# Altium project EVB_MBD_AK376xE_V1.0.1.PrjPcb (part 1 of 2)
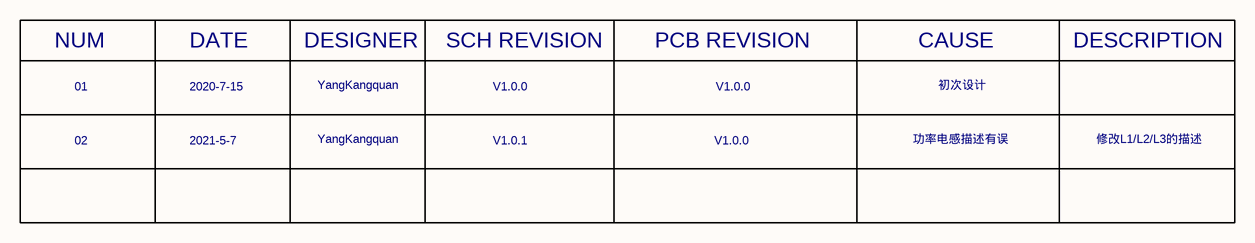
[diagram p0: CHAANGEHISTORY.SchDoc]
8 sheets, 331 parts. Net scope: flat (ports and power ports of the same name join across sheets).
Sheets:
  CHAANGEHISTORY.SchDoc
  BLOCK_DIAGRAM.SchDoc
  INTERFACE_CORE.SchDoc
  POWER.SchDoc
  TF_PA_UART.SchDoc
  MAC_EMMC_USBWIFI.SchDoc
  LCD.SchDoc
  JTAG_I2S_KEY.SchDoc

## Sheet CHAANGEHISTORY.SchDoc: EVB_MBD_AK376xE_V1.0.1
size A3; Revision: V1.0.1; SheetNumber: 1; SheetTotal: 8

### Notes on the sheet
- NUM
- 01
- DATE
- 2020-7-15
- DESIGNER
- YangKangquan
- SCH REVISION
- V1.0.0
- PCB REVISION
- CAUSE
- 初次设计
- DESCRIPTION
- 02
- 2021-5-7
- V1.0.1
- 功率电感描述有误
- 修改L1/L2/L3的描述

## Sheet BLOCK_DIAGRAM.SchDoc: EVB_MBD_AK376xE_V1.0.1
size A3; Revision: V1.0.1; SheetNumber: 2; SheetTotal: 8
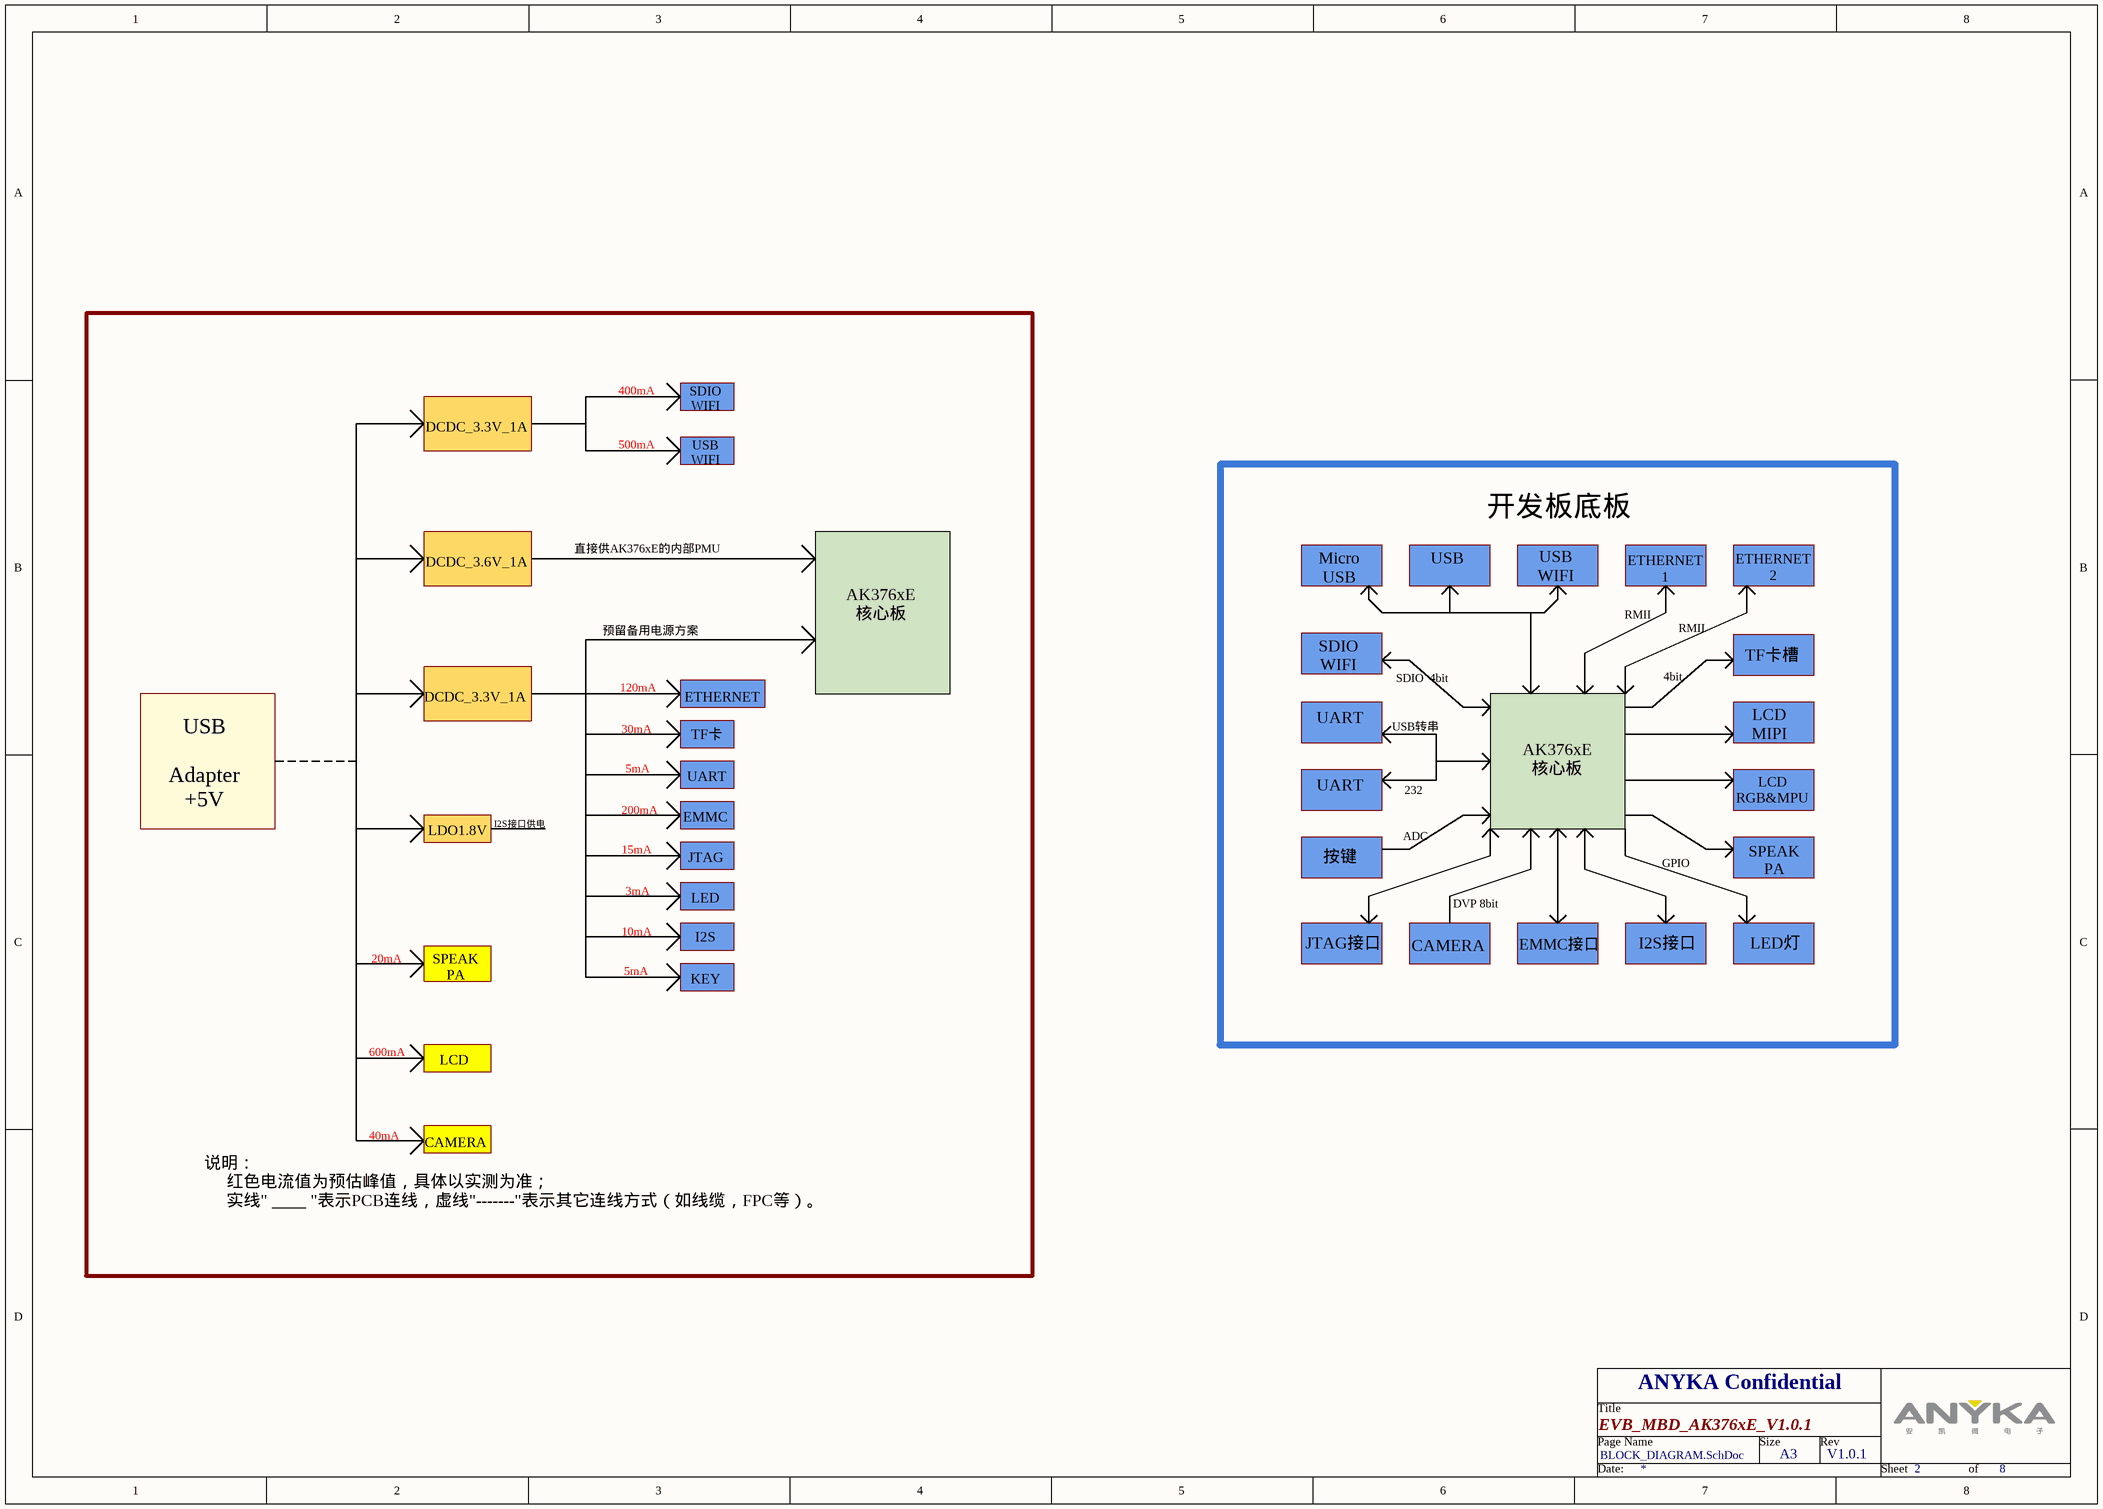
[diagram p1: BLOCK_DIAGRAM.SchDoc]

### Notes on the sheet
- DCDC_3.3V_1A
- 400mA
- 500mA
- SDIO
  WIFI
- USB
  WIFI
- DCDC_3.6V_1A
- 直接供AK376xE的内部PMU
- Micro
  USB
- USB
  HOST
- 开发板底板
- ETHERNET
  1
- ETHERNET
  2
- 预留备用电源方案
- AK376xE
  核心板
- RMII
- 120mA
- ETHERNET
- SDIO  4bit
- 4bit
- TF卡槽
- 30mA
- 5mA
- TF卡
- UART
- UART
  USB
- USB转串
- LCD
  MIPI
- USB
  Adapter
  +5V
- LDO1.8V
- I2S接口供电
- 15mA
- 200mA
- EMMC
- JTAG
- UART
  DB9
- ADC
- 232
- LCD
  RGB&MPU
- 3mA
- LED
- 按键
- DVP 8bit
- GPIO
- SPEAK
  PA
- 20mA
- 10mA
- I2S
- KEY
- JTAG接口
- CAMERA
- EMMC接口
- I2S接口
- LED灯
- 600mA
- LCD
- 40mA
- 说明：
  红色电流值为预估峰值，具体以实测为准；
  实线" ____ "表示PCB连线，虚线"-------"表示其它连线方式（如线缆，FPC等）。

## Sheet INTERFACE_CORE.SchDoc: EVB_MBD_AK376xE_V1.0.1
size A3; Revision: V1.0.1; SheetNumber: 3; SheetTotal: 8
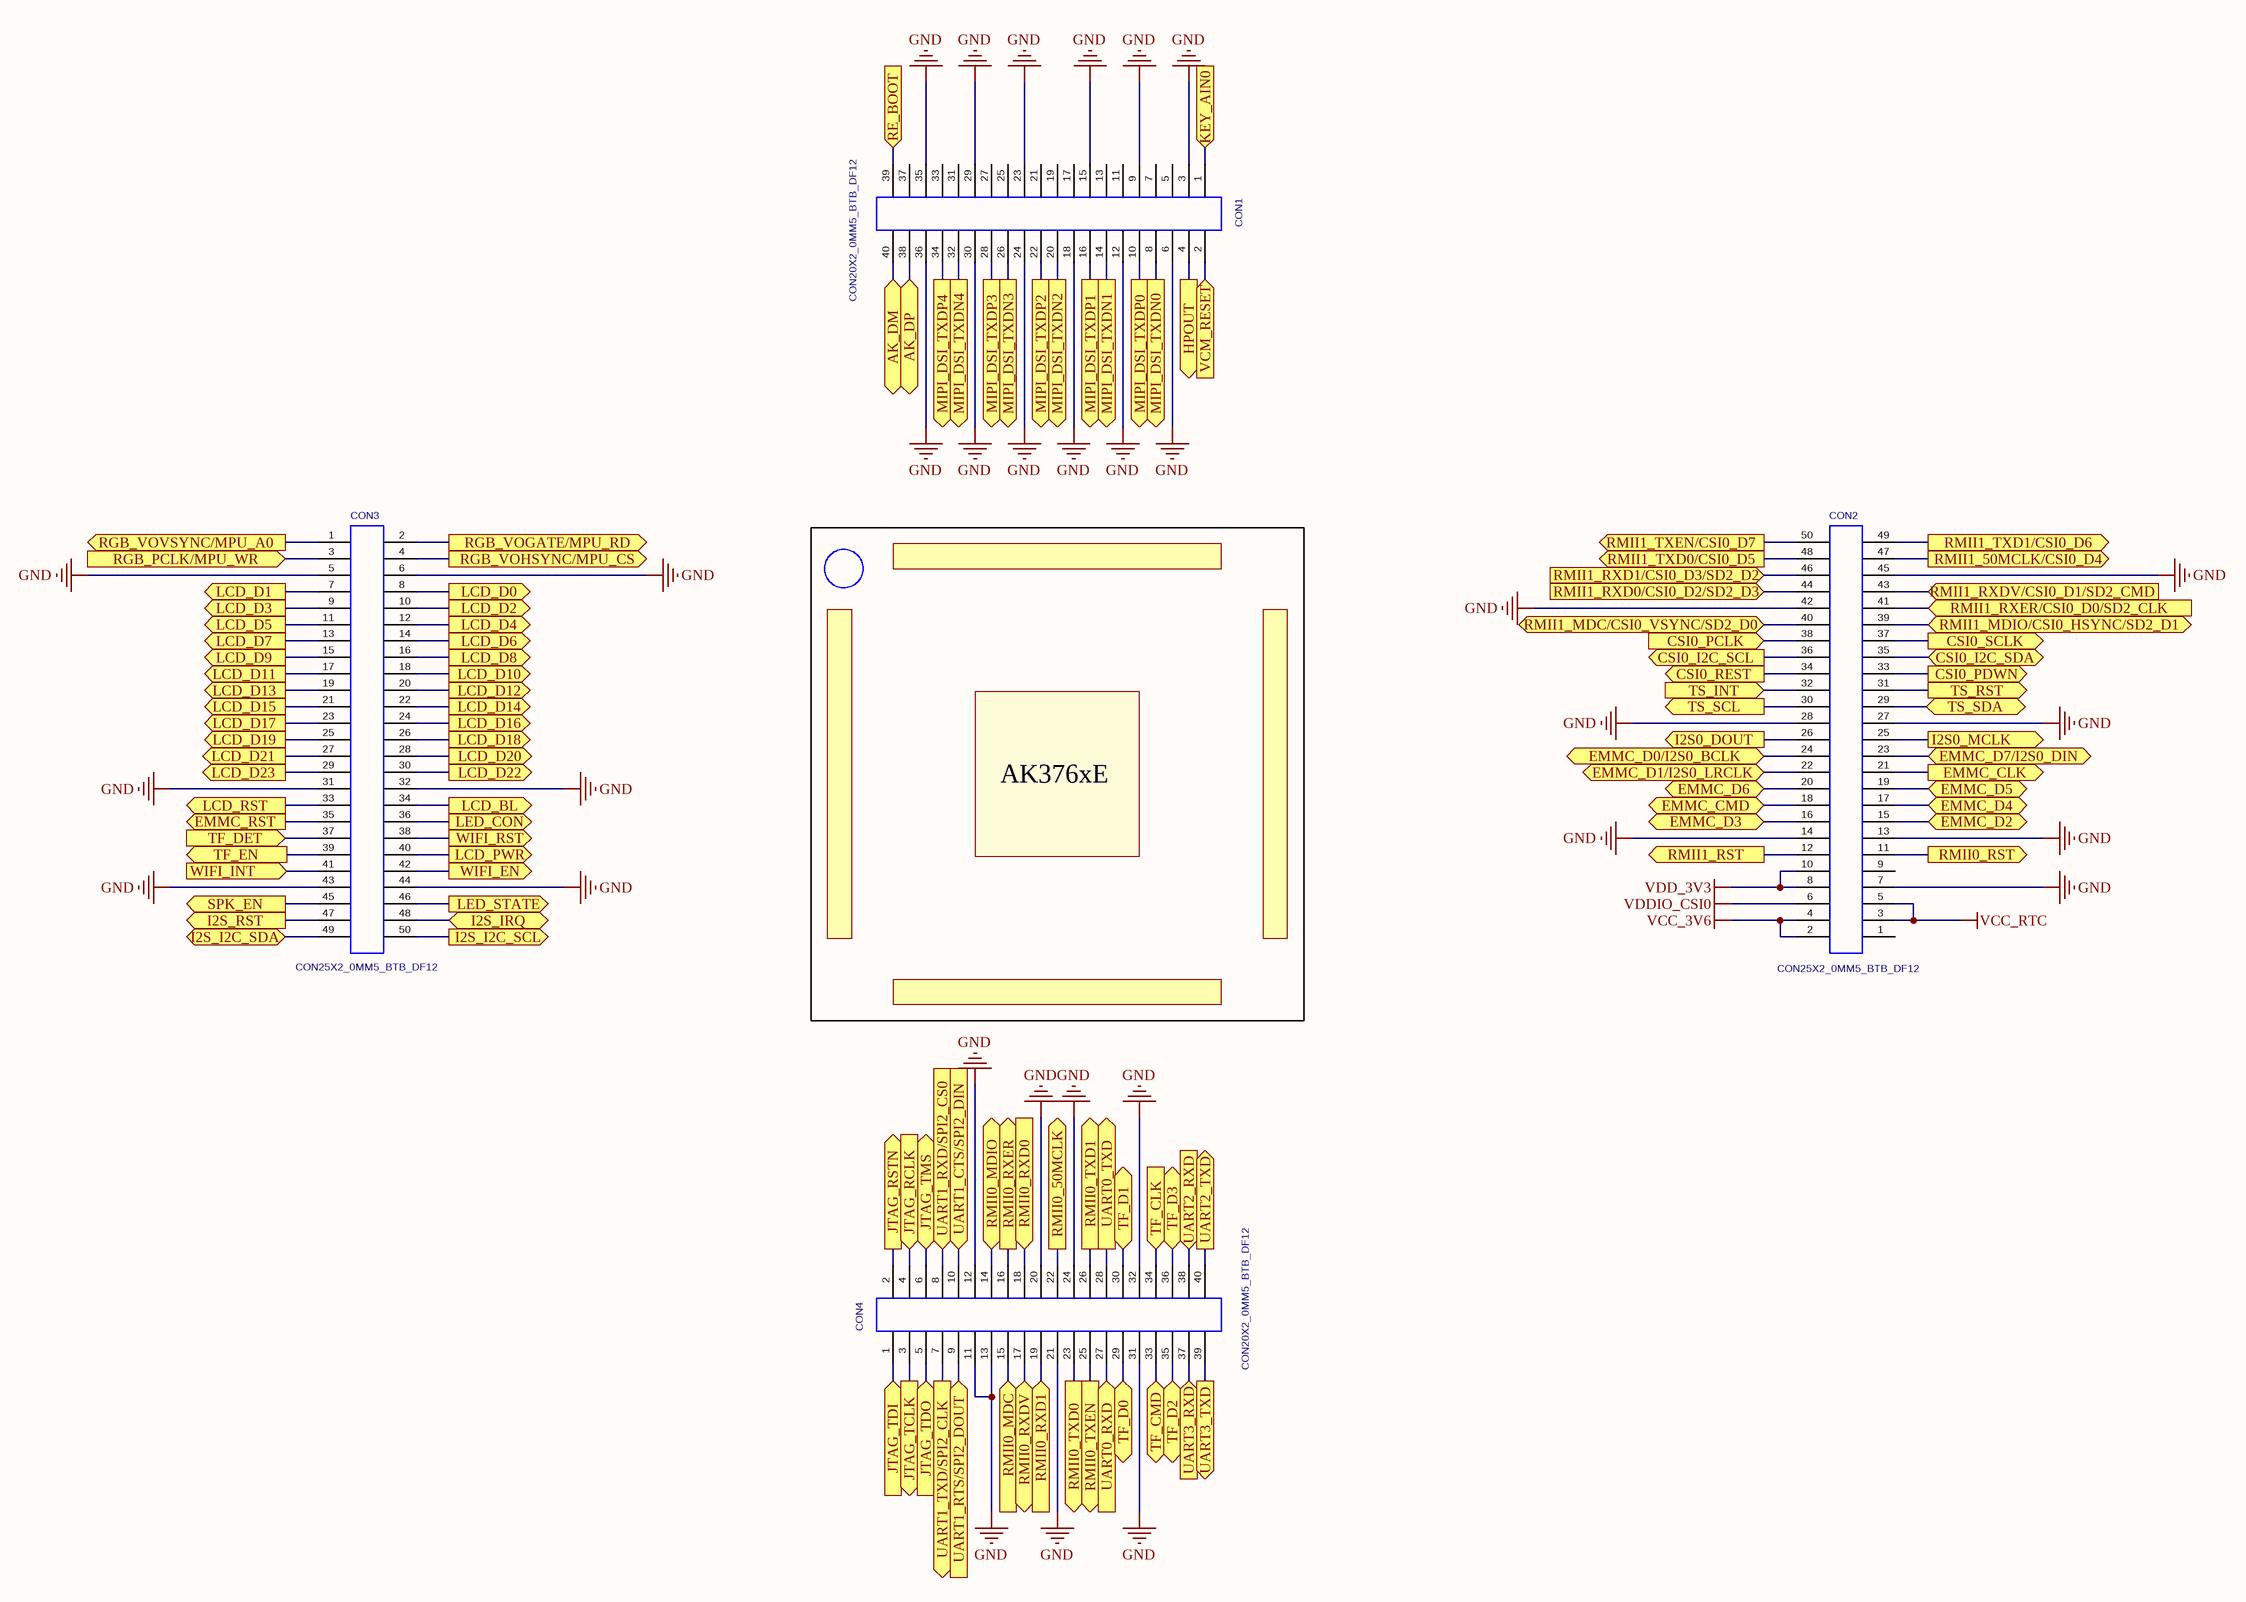
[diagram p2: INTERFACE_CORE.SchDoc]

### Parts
CON1  CON20X2_0MM5_BTB_DF12  [CON20X2_0MM5_BTB_DF12_P]
CON2  CON25X2_0MM5_BTB_DF12  [CON25X2_0MM5_BTB_DF12_P]
CON3  CON25X2_0MM5_BTB_DF12  [CON25X2_0MM5_BTB_DF12_P]
CON4  CON20X2_0MM5_BTB_DF12  [CON20X2_0MM5_BTB_DF12_P]

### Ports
AK_DM (bidir), AK_DP (bidir), CSI0_I2C_SCL (out), CSI0_I2C_SDA (bidir), CSI0_PCLK (in), CSI0_PDWN (out), CSI0_REST (out), CSI0_SCLK (out), EMMC_CLK (out), EMMC_CMD (bidir), EMMC_D0/I2S0_BCLK (bidir), EMMC_D1/I2S0_LRCLK (bidir), EMMC_D2 (bidir), EMMC_D3 (bidir), EMMC_D4 (bidir), EMMC_D5 (bidir), EMMC_D6 (bidir), EMMC_D7/I2S0_DIN (bidir), EMMC_RST (out), HPOUT (out), I2S0_DOUT (out), I2S0_MCLK (out), I2S_I2C_SCL (out), I2S_I2C_SDA (bidir), I2S_IRQ (bidir), I2S_RST (out), JTAG_RCLK (in), JTAG_RSTN (out), JTAG_TCLK (out), JTAG_TDI (in), JTAG_TDO (in), JTAG_TMS (bidir), KEY_AIN0 (in), LCD_BL (out), LCD_D0 (out), LCD_D1 (out), LCD_D2 (out), LCD_D3 (out), LCD_D4 (out), LCD_D5 (out), LCD_D6 (out), LCD_D7 (out), LCD_D8 (out), LCD_D9 (out), LCD_D10 (out), LCD_D11 (out), LCD_D12 (out), LCD_D13 (out), LCD_D14 (out), LCD_D15 (out), LCD_D16 (out), LCD_D17 (out), LCD_D18 (out), LCD_D19 (out), LCD_D20 (out), LCD_D21 (out), LCD_D22 (out), LCD_D23 (out), LCD_PWR (out), LCD_RST (out), LED_CON (out), LED_STATE (out), MIPI_DSI_TXDN0 (out), MIPI_DSI_TXDN1 (out), MIPI_DSI_TXDN2 (out), MIPI_DSI_TXDN3 (out), MIPI_DSI_TXDN4 (out), MIPI_DSI_TXDP0 (out), MIPI_DSI_TXDP1 (out), MIPI_DSI_TXDP2 (out), MIPI_DSI_TXDP3 (out), MIPI_DSI_TXDP4 (out), RE_BOOT (in), RGB_PCLK/MPU_WR (in), RGB_VOGATE/MPU_RD (out), RGB_VOHSYNC/MPU_CS (out), RGB_VOVSYNC/MPU_A0 (out), RMII0_50MCLK (out), RMII0_MDC (in), RMII0_MDIO (bidir), RMII0_RST (out), RMII0_RXD0 (in), RMII0_RXD1 (in), RMII0_RXDV (bidir), RMII0_RXER (out), RMII0_TXD0 (out), RMII0_TXD1 (out), RMII0_TXEN (out), RMII1_50MCLK/CSI0_D4 (out), RMII1_MDC/CSI0_VSYNC/SD2_D0 (bidir), RMII1_MDIO/CSI0_HSYNC/SD2_D1 (bidir), RMII1_RST (out), RMII1_RXD0/CSI0_D2/SD2_D3 (in), RMII1_RXD1/CSI0_D3/SD2_D2 (in), RMII1_RXDV/CSI0_D1/SD2_CMD (in), RMII1_RXER/CSI0_D0/SD2_CLK (in), RMII1_TXD0/CSI0_D5 (out), RMII1_TXD1/CSI0_D6 (out), RMII1_TXEN/CSI0_D7 (out), SPK_EN (out), TF_CLK (in), TF_CMD (bidir), TF_D0 (bidir), TF_D1 (bidir), TF_D2 (bidir), TF_D3 (bidir), TF_DET (in), TF_EN (out), TS_INT (in), TS_RST (out), TS_SCL (out), TS_SDA (bidir), UART0_RXD (in), UART0_TXD (out), UART1_CTS/SPI2_DIN (in), UART1_RTS/SPI2_DOUT (in), UART1_RXD/SPI2_CS0 (in), UART1_TXD/SPI2_CLK (out), UART2_RXD (in), UART2_TXD (out), UART3_RXD (in), UART3_TXD (out), VCM_RESET (in), WIFI_EN (out), WIFI_INT (in), WIFI_RST (out)

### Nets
GND: CON1.3 CON1.6 CON1.9 CON1.12 CON1.15 CON1.18 CON1.23 CON1.24 CON1.29 CON1.30 CON1.35 CON1.36 CON2.7 CON2.13 CON2.14 CON2.27 CON2.28 CON2.42 CON2.45 CON3.5 CON3.6 CON3.31 CON3.32 CON3.43 CON3.44 CON4.11 CON4.12 CON4.13 CON4.20 CON4.21 CON4.24 CON4.31 CON4.32
VCC_3V6: CON2.2 CON2.4
VCC_RTC: CON2.3 CON2.5
VDD_3V3: CON2.8 CON2.10
VDDIO_CSI0: CON2.6
AK_DM: CON1.40 ; port AK_DM
AK_DP: CON1.38 ; port AK_DP
CSI0_I2C_SCL: CON2.36 ; port CSI0_I2C_SCL
CSI0_I2C_SDA: CON2.35 ; port CSI0_I2C_SDA
CSI0_PCLK: CON2.38 ; port CSI0_PCLK
CSI0_PDWN: CON2.33 ; port CSI0_PDWN
CSI0_REST: CON2.34 ; port CSI0_REST
CSI0_SCLK: CON2.37 ; port CSI0_SCLK
EMMC_CLK: CON2.21 ; port EMMC_CLK
EMMC_CMD: CON2.18 ; port EMMC_CMD
EMMC_D0/I2S0_BCLK: CON2.24 ; port EMMC_D0/I2S0_BCLK
EMMC_D1/I2S0_LRCLK: CON2.22 ; port EMMC_D1/I2S0_LRCLK
EMMC_D2: CON2.15 ; port EMMC_D2
EMMC_D3: CON2.16 ; port EMMC_D3
EMMC_D4: CON2.17 ; port EMMC_D4
EMMC_D5: CON2.19 ; port EMMC_D5
EMMC_D6: CON2.20 ; port EMMC_D6
EMMC_D7/I2S0_DIN: CON2.23 ; port EMMC_D7/I2S0_DIN
EMMC_RST: CON3.35 ; port EMMC_RST
HPOUT: CON1.4 ; port HPOUT
I2S0_DOUT: CON2.26 ; port I2S0_DOUT
I2S0_MCLK: CON2.25 ; port I2S0_MCLK
I2S_I2C_SCL: CON3.50 ; port I2S_I2C_SCL
I2S_I2C_SDA: CON3.49 ; port I2S_I2C_SDA
I2S_IRQ: CON3.48 ; port I2S_IRQ
I2S_RST: CON3.47 ; port I2S_RST
JTAG_RCLK: CON4.4 ; port JTAG_RCLK
JTAG_RSTN: CON4.2 ; port JTAG_RSTN
JTAG_TCLK: CON4.3 ; port JTAG_TCLK
JTAG_TDI: CON4.1 ; port JTAG_TDI
JTAG_TDO: CON4.5 ; port JTAG_TDO
JTAG_TMS: CON4.6 ; port JTAG_TMS
LCD_BL: CON3.34 ; port LCD_BL
LCD_D0: CON3.8 ; port LCD_D0
LCD_D1: CON3.7 ; port LCD_D1
LCD_D2: CON3.10 ; port LCD_D2
LCD_D3: CON3.9 ; port LCD_D3
LCD_D4: CON3.12 ; port LCD_D4
LCD_D5: CON3.11 ; port LCD_D5
LCD_D6: CON3.14 ; port LCD_D6
LCD_D7: CON3.13 ; port LCD_D7
LCD_D8: CON3.16 ; port LCD_D8
LCD_D9: CON3.15 ; port LCD_D9
LCD_D10: CON3.18 ; port LCD_D10
LCD_D11: CON3.17 ; port LCD_D11
LCD_D12: CON3.20 ; port LCD_D12
LCD_D13: CON3.19 ; port LCD_D13
LCD_D14: CON3.22 ; port LCD_D14
LCD_D15: CON3.21 ; port LCD_D15
LCD_D16: CON3.24 ; port LCD_D16
LCD_D17: CON3.23 ; port LCD_D17
LCD_D18: CON3.26 ; port LCD_D18
LCD_D19: CON3.25 ; port LCD_D19
LCD_D20: CON3.28 ; port LCD_D20
LCD_D21: CON3.27 ; port LCD_D21
LCD_D22: CON3.30 ; port LCD_D22
LCD_D23: CON3.29 ; port LCD_D23
LCD_PWR: CON3.40 ; port LCD_PWR
LCD_RST: CON3.33 ; port LCD_RST
LED_CON: CON3.36 ; port LED_CON
LED_STATE: CON3.46 ; port LED_STATE
MIPI_DSI_TXDN0: CON1.8 ; port MIPI_DSI_TXDN0
MIPI_DSI_TXDN1: CON1.14 ; port MIPI_DSI_TXDN1
MIPI_DSI_TXDN2: CON1.20 ; port MIPI_DSI_TXDN2
MIPI_DSI_TXDN3: CON1.26 ; port MIPI_DSI_TXDN3
MIPI_DSI_TXDN4: CON1.32 ; port MIPI_DSI_TXDN4
MIPI_DSI_TXDP0: CON1.10 ; port MIPI_DSI_TXDP0
MIPI_DSI_TXDP1: CON1.16 ; port MIPI_DSI_TXDP1
MIPI_DSI_TXDP2: CON1.22 ; port MIPI_DSI_TXDP2
MIPI_DSI_TXDP3: CON1.28 ; port MIPI_DSI_TXDP3
MIPI_DSI_TXDP4: CON1.34 ; port MIPI_DSI_TXDP4
RE_BOOT: CON1.39 ; port RE_BOOT
RGB_PCLK/MPU_WR: CON3.3 ; port RGB_PCLK/MPU_WR
RGB_VOGATE/MPU_RD: CON3.2 ; port RGB_VOGATE/MPU_RD
RGB_VOHSYNC/MPU_CS: CON3.4 ; port RGB_VOHSYNC/MPU_CS
RGB_VOVSYNC/MPU_A0: CON3.1 ; port RGB_VOVSYNC/MPU_A0
RMII0_50MCLK: CON4.22 ; port RMII0_50MCLK
RMII0_MDC: CON4.15 ; port RMII0_MDC
RMII0_MDIO: CON4.14 ; port RMII0_MDIO
RMII0_RST: CON2.11 ; port RMII0_RST
RMII0_RXD0: CON4.18 ; port RMII0_RXD0
RMII0_RXD1: CON4.19 ; port RMII0_RXD1
RMII0_RXDV: CON4.17 ; port RMII0_RXDV
RMII0_RXER: CON4.16 ; port RMII0_RXER
RMII0_TXD0: CON4.23 ; port RMII0_TXD0
RMII0_TXD1: CON4.26 ; port RMII0_TXD1
RMII0_TXEN: CON4.25 ; port RMII0_TXEN
RMII1_RST: CON2.12 ; port RMII1_RST
SPK_EN: CON3.45 ; port SPK_EN
TF_CMD: CON4.33 ; port TF_CMD
TF_D0: CON4.29 ; port TF_D0
TF_D1: CON4.30 ; port TF_D1
TF_D2: CON4.35 ; port TF_D2
TF_D3: CON4.36 ; port TF_D3
TF_DET: CON3.37 ; port TF_DET
TF_EN: CON3.39 ; port TF_EN
TF_MCK: CON4.34 ; port TF_CLK
TS_INT: CON2.32 ; port TS_INT
TS_RST: CON2.31 ; port TS_RST
TS_SCL: CON2.30 ; port TS_SCL
TS_SDA: CON2.29 ; port TS_SDA
UART0_RXD: CON4.27 ; port UART0_RXD
UART0_TXD: CON4.28 ; port UART0_TXD
UART1_CTS/SPI2_DIN: CON4.10 ; port UART1_CTS/SPI2_DIN
UART1_RTS/SPI2_DOUT: CON4.9 ; port UART1_RTS/SPI2_DOUT
UART1_RXD/SPI2_CS0: CON4.8 ; port UART1_RXD/SPI2_CS0
UART1_TXD/SPI2_CLK: CON4.7 ; port UART1_TXD/SPI2_CLK
UART2_RXD: CON4.38 ; port UART2_RXD
UART2_TXD: CON4.40 ; port UART2_TXD
UART3_RXD: CON4.37 ; port UART3_RXD
UART3_TXD: CON4.39 ; port UART3_TXD
WIFI_EN: CON3.42 ; port WIFI_EN
WIFI_INT: CON3.41 ; port WIFI_INT
WIFI_RST: CON3.38 ; port WIFI_RST
NetC86_1: CON1.2 ; port VCM_RESET
NetCON1_1: CON1.1 ; port KEY_AIN0
NetCON2_39: CON2.39 ; port RMII1_MDIO/CSI0_HSYNC/SD2_D1
NetCON2_40: CON2.40 ; port RMII1_MDC/CSI0_VSYNC/SD2_D0
NetCON2_41: CON2.41 ; port RMII1_RXER/CSI0_D0/SD2_CLK
NetCON2_43: CON2.43 ; port RMII1_RXDV/CSI0_D1/SD2_CMD
NetCON2_44: CON2.44 ; port RMII1_RXD0/CSI0_D2/SD2_D3
NetCON2_46: CON2.46 ; port RMII1_RXD1/CSI0_D3/SD2_D2
NetCON2_47: CON2.47 ; port RMII1_50MCLK/CSI0_D4
NetCON2_48: CON2.48 ; port RMII1_TXD0/CSI0_D5
NetCON2_49: CON2.49 ; port RMII1_TXD1/CSI0_D6
NetCON2_50: CON2.50 ; port RMII1_TXEN/CSI0_D7

Not connected (* = marked no-connect by the designer): CON1 5 7 11 13 17 19 21 25 27 31 33 37; CON2 1 9

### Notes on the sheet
- AK376xE

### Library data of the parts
CON1 CON4 = CNBBF4000XX: Connector 0.5mm ，BTB2*20Pin，SMT，母座，H3.0，DF12#(3.0)-40DP-0.5;
CON2 CON3 = CNBBF5000XX: Connector： 0.5mm ，BTB2*25Pin，SMT，母座，H3.0，DF12#(3.0)-50DP-0.5;

## Sheet POWER.SchDoc: EVB_MBD_AK376xE_V1.0.1
size A3; Revision: V1.0.1; SheetNumber: 4; SheetTotal: 8
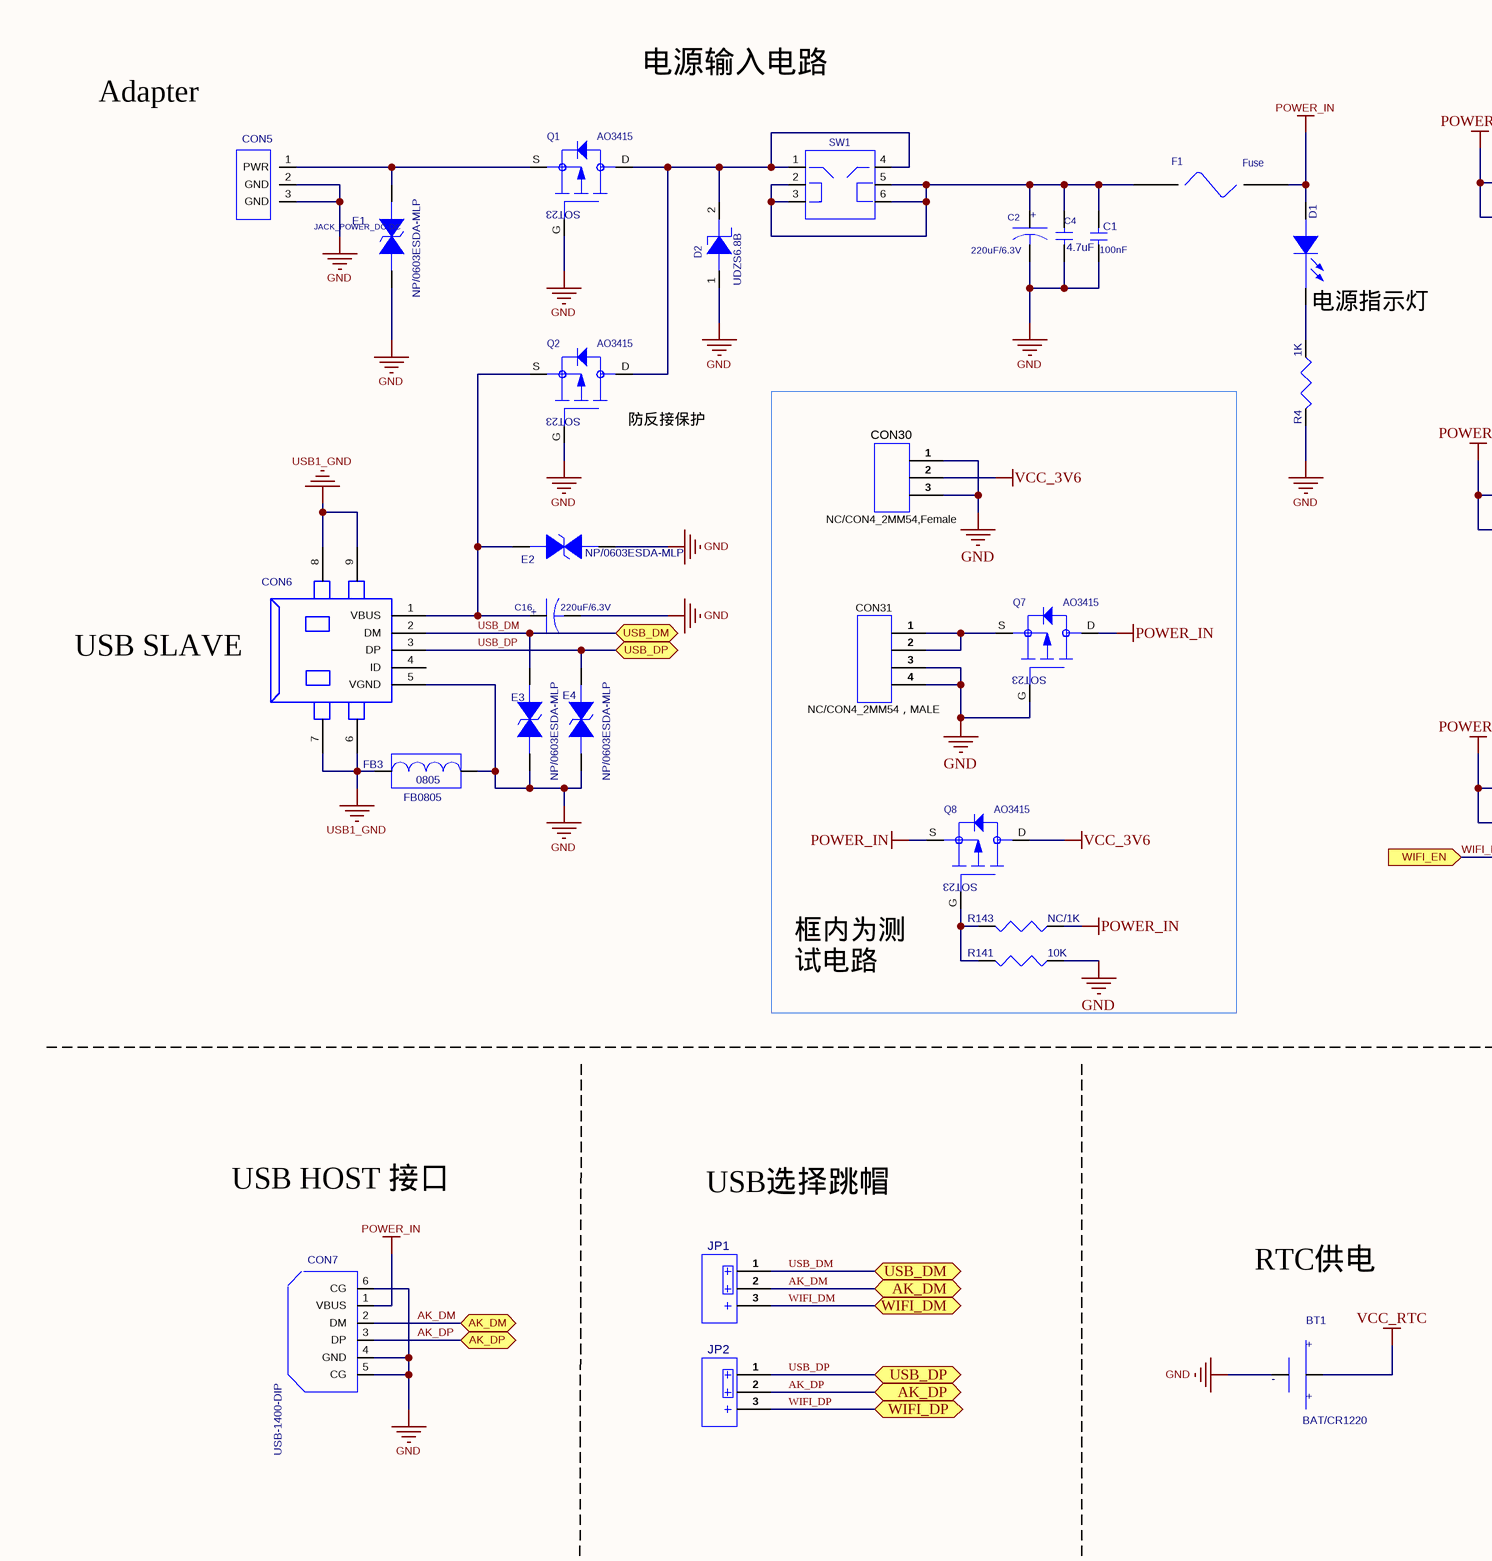
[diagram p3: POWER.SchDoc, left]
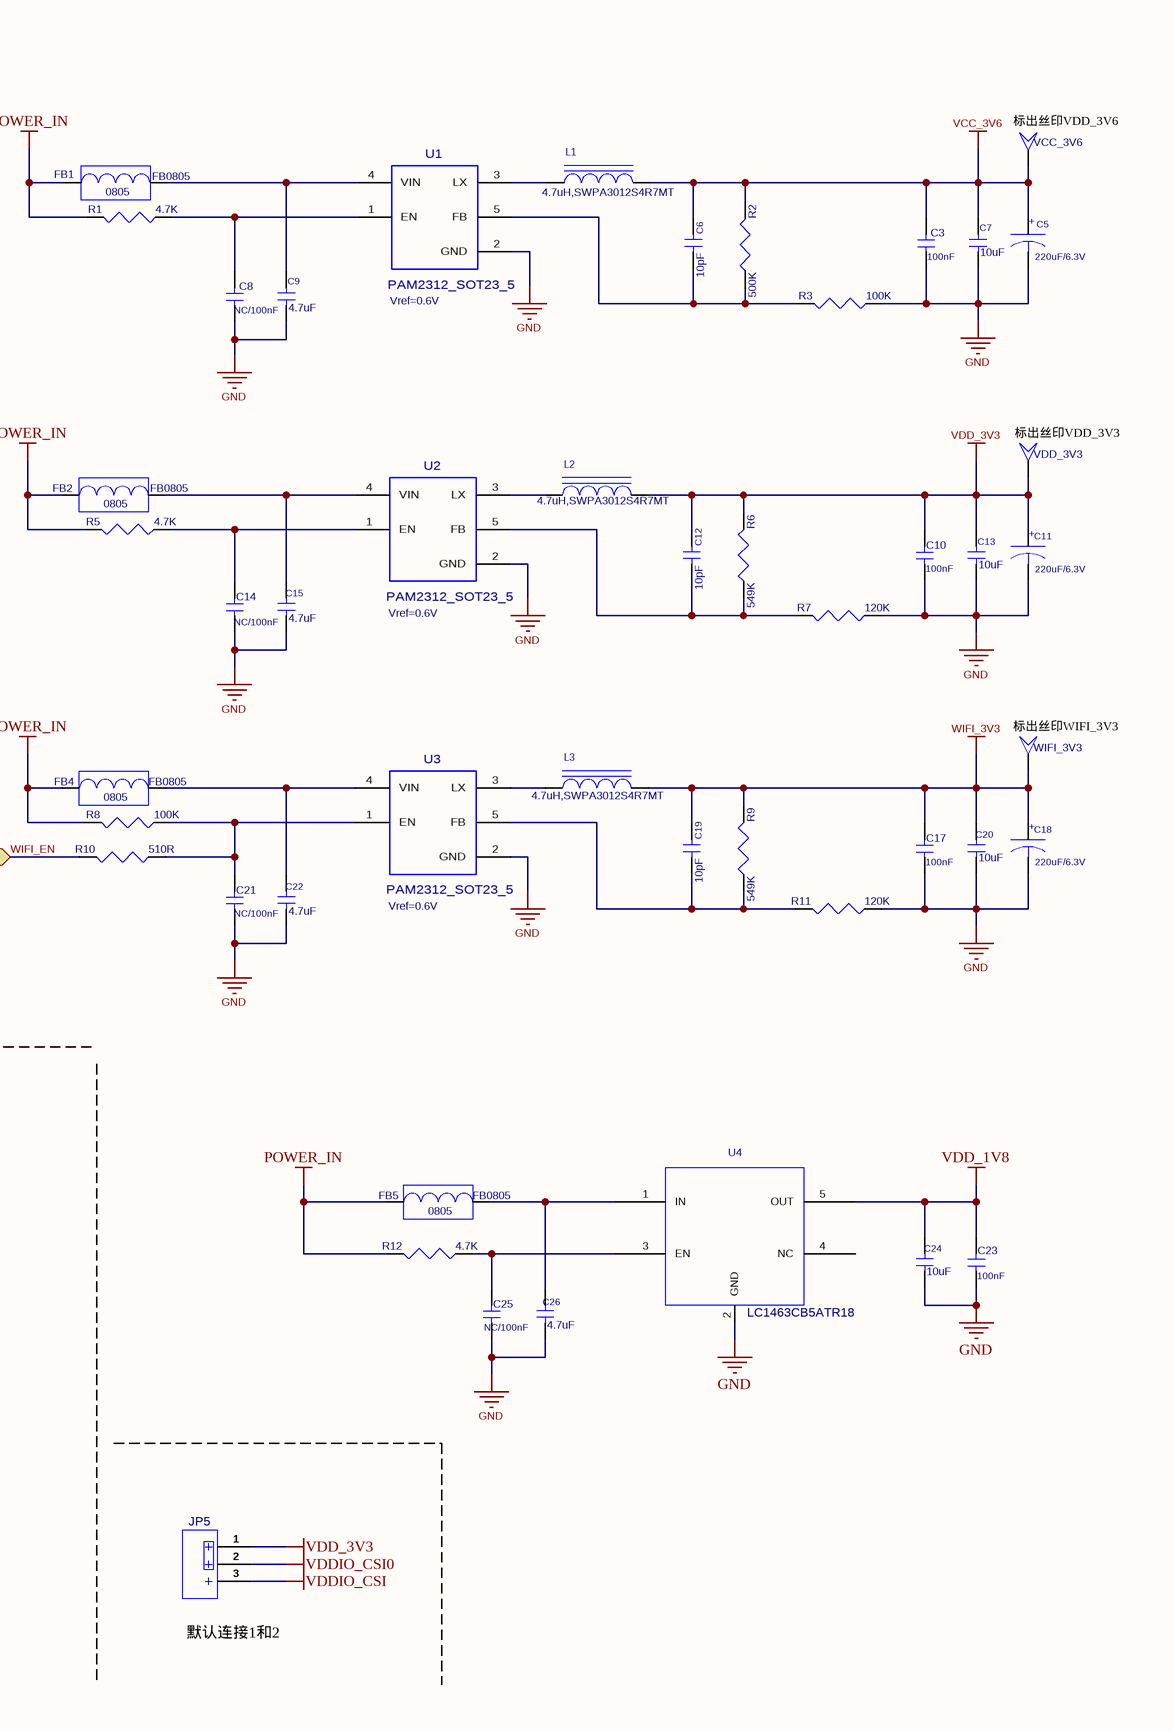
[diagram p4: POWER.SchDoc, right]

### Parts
BT1  value BAT/CR1220  [BAT_CR1220]  (hidden comment: BAT_CR1220)
C1  value 100nF  [C0603]  (hidden comment: C0603)
C2  value 220uF/6.3V  [C3528]  (hidden comment: 220uF)
C3  value 100nF  [C0603]  (hidden comment: C0603)
C4  4.7uF  [C0603]
C5  value 220uF/6.3V  [C3528]  (hidden comment: 220uF)
C6  10pF  [C0603]
C7  10uF  [C0603]
C8  value NC/100nF  [C0603]  (hidden comment: C0603)
C9  4.7uF  [C0603]
C10  value 100nF  [C0603]  (hidden comment: C0603)
C11  value 220uF/6.3V  [C3528]  (hidden comment: 220uF)
C12  10pF  [C0603]
C13  10uF  [C0603]
C14  value NC/100nF  [C0603]  (hidden comment: C0603)
C15  4.7uF  [C0603]
C16  value 220uF/6.3V  [C3528]  (hidden comment: 220uF)
C17  value 100nF  [C0603]  (hidden comment: C0603)
C18  value 220uF/6.3V  [C3528]  (hidden comment: 220uF)
C19  10pF  [C0603]
C20  10uF  [C0603]
C21  value NC/100nF  [C0603]  (hidden comment: C0603)
C22  4.7uF  [C0603]
C23  value 100nF  [C0603]  (hidden comment: C0603)
C24  10uF  [C0603]
C25  value NC/100nF  [C0603]  (hidden comment: C0603)
C26  4.7uF  [C0603]
CON5  CNDCF0302  [CNDCF0302]  (value not drawn)
CON6  USB_MICRO-5P/F_SMT  [USB_MICRO_5P/F_SMT]  (value not drawn)
CON7  USB-1400-DIP  [USB-1400-DIP]  (value not drawn)
CON30  NC/CON4_2MM54,Female  [CON3_2MM54]
CON31  NC/CON4_2MM54，MALE  [CON4_2MM54]
D1  REDLED  [LED0603]  (value not drawn)
D2  UDZS6.8B  [UDZS6.8B]
E1  value NP/0603ESDA-MLP  [ESD0603]  (hidden comment: ESD0603)
E2  value NP/0603ESDA-MLP  [ESD0603]  (hidden comment: ESD0603)
E3  value NP/0603ESDA-MLP  [ESD0603]  (hidden comment: ESD0603)
E4  value NP/0603ESDA-MLP  [ESD0603]  (hidden comment: ESD0603)
F1  value Fuse  [FUSE1206]  (hidden comment: FUSE1206)
FB1  FB0805  [FB0805]
FB2  FB0805  [FB0805]
FB3  FB0805  [FB0805]
FB4  FB0805  [FB0805]
FB5  FB0805  [FB0805]
JP1  SIP_3P_2MM54，MALE  [CON3_2MM54]  (value not drawn)
JP2  SIP_3P_2MM54，MALE  [CON3_2MM54]  (value not drawn)
JP5  SIP_3P_2MM54，MALE  [CON3_2MM54]  (value not drawn)
L1  4.7uH,SWPA3012S4R7MT  [L_SWPA3012_3X3MM]
L2  4.7uH,SWPA3012S4R7MT  [L_SWPA3012_3X3MM]
L3  4.7uH,SWPA3012S4R7MT  [L_SWPA3012_3X3MM]
Q1  AO3415  [SOT23_GDS]
Q2  AO3415  [SOT23_GDS]
Q7  AO3415  [SOT23_GDS]
Q8  AO3415  [SOT23_GDS]
R1  4.7K  [R0603]
R2  500K  [R0603]
R3  100K  [R0603]
R4  1K  [R0402]
R5  4.7K  [R0603]
R6  549K  [R0603]
R7  120K  [R0603]
R8  100K  [R0603]
R9  549K  [R0603]
R10  510R  [R0603]
R11  120K  [R0603]
R12  4.7K  [R0603]
R141  10K  [R0603]
R143  NC/1K  [R0603]
SW1  SWITCH_POWER_DC  [SWITCH_POWER_DC]  (value not drawn)
U1  PAM2312_SOT23_5  [PAM2312_SOT23_5]
U2  PAM2312_SOT23_5  [PAM2312_SOT23_5]
U3  PAM2312_SOT23_5  [PAM2312_SOT23_5]
U4  value LC1463CB5ATR18  [LC1463CB5ATR18_SOT23-5]  (hidden comment: LC1463CB5ATR18_SOT23-5)
VCC_3V6  TP40  [TP40]  (value not drawn)
VDD_3V3  TP40  [TP40]  (value not drawn)
WIFI_3V3  TP40  [TP40]  (value not drawn)

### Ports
AK_DM (bidir), AK_DP (bidir), USB_DM (bidir), USB_DP (bidir), WIFI_DM (bidir), WIFI_DP (bidir), WIFI_EN (in)

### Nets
GND: BT1.2(-) C1.1 C2.2 C3.1 C4.2 C5.2 C7.2 C8.1 C9.2 C10.1 C11.2 C13.2 C14.1 C15.2 C16.2 C17.1 C18.2 C20.2 C21.1 C22.2 C23.1 C24.2 C25.1 C26.2 CON5.2(GND) CON5.3(GND) CON6.5(VGND) CON7.4(GND) CON7.5(CG) CON7.6(CG) CON30.1 CON30.3 CON31.3 CON31.4 D2.1(A) E1.2 E2.2 E3.2 E4.2 FB3.2 Q1.G Q2.G Q7.G R3.1 R4.2 R7.1 R11.1 R141.1 U1.2(GND) U2.2(GND) U3.2(GND) U4.2(GND)
POWER_IN: CON7.1(VBUS) D1.A F1.2 FB1.1 FB2.1 FB4.1 FB5.1 Q7.D Q8.S R1.2 R5.2 R8.2 R12.2 R143.1
USB1_GND: CON6.6 CON6.7 CON6.8 CON6.9 FB3.1
VCC_3V6: C3.2 C5.1 C6.1 C7.1 CON30.2 L1.2 Q8.D R2.2 VCC_3V6.1
VCC_RTC: BT1.1(+)
VDD_1V8: C23.2 C24.1 U4.5(OUT)
VDD_3V3: C10.2 C11.1 C12.1 C13.1 JP5.1 L2.2 R6.2 VDD_3V3.1
VDDIO_CSI: JP5.3
VDDIO_CSI0: JP5.2
WIFI_3V3: C17.2 C18.1 C19.1 C20.1 L3.2 R9.2 WIFI_3V3.1
AK_DM: CON7.2(DM) JP1.2 ; port AK_DM
AK_DP: CON7.3(DP) JP2.2 ; port AK_DP
USB_DM: CON6.2(DM) E3.1 JP1.1 ; port USB_DM
USB_DP: CON6.3(DP) E4.1 JP2.1 ; port USB_DP
WIFI_DM: JP1.3 ; port WIFI_DM
WIFI_DP: JP2.3 ; port WIFI_DP
WIFI_EN: R10.2 ; port WIFI_EN
NetC1_2: C1.2 C2.1 C4.1 F1.1 SW1.2 SW1.3 SW1.5 SW1.6
NetC6_2: C6.2 R2.1 R3.2 U1.5(FB)
NetC8_2: C8.2 R1.1 U1.1(EN)
NetC9_1: C9.1 FB1.2 U1.4(VIN)
NetC12_2: C12.2 R6.1 R7.2 U2.5(FB)
NetC14_2: C14.2 R5.1 U2.1(EN)
NetC15_1: C15.1 FB2.2 U2.4(VIN)
NetC16_1: C16.1 CON6.1(VBUS) E2.1 Q2.S
NetC19_2: C19.2 R9.1 R11.2 U3.5(FB)
NetC21_2: C21.2 R8.1 R10.1 U3.1(EN)
NetC22_1: C22.1 FB4.2 U3.4(VIN)
NetC25_2: C25.2 R12.1 U4.3(EN)
NetC26_1: C26.1 FB5.2 U4.1(IN)
NetCON5_1: CON5.1(PWR) E1.1 Q1.S
NetCON31_1: CON31.1 CON31.2 Q7.S
NetD1_K: D1.K R4.1
NetD2_2: D2.2(K) Q1.D Q2.D SW1.1 SW1.4
NetL1_1: L1.1 U1.3(LX)
NetL2_1: L2.1 U2.3(LX)
NetL3_1: L3.1 U3.3(LX)
NetQ8_G: Q8.G R141.2 R143.2

Not connected (* = marked no-connect by the designer): CON6 4(ID); U4 4(NC)

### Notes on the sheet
- Adapter
- 电源输入电路
- (near VCC_3V6) 标出丝印VDD_3V6
- (near U1) Vref=0.6V
- (near D1) 电源指示灯
- (near Q2) 防反接保护
- (near VDD_3V3) 标出丝印VDD_3V3
- (near U2) Vref=0.6V
- USB SLAVE
- (near WIFI_3V3) 标出丝印WIFI_3V3
- (near U3) Vref=0.6V
- (near Q8) 框内为测试电路
- USB HOST 接口
- USB选择跳帽
- RTC供电
- (near JP5) 默认连接1和2

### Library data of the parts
BT1 = CNBAF0000XX: CR1220-2，SMD 3V纽扣电池座子，棕色; Part Number_AK: CNBAF0200XX; SOURCE_PATH: D:\PROGRAM FILES\ORCAD\ORCAD_10.5\TOOLS\CAPTURE\LIBRARY\DISCRETE.OLB; Catalog: Connector
C1 C3 C10 C17 C23 = CC0301040XX: C/C,100nF,25V,+/-5%,0603; Catalog: 陶瓷电容
C2 C5 C11 C16 C18 = TC2802271XX: T/C,220uF,6.3V,+/-5%,3528; Catalog: 钽电容
C4 C9 C15 C22 C26 = CC0304750XX: C/C,4.7uF,25V,+/-5%,0603; Catalog: 陶瓷电容
C6 C12 C19 = CC0301000XX: C/C,10pF,25V,+/-5%,0603; Catalog: 陶瓷电容
C7 C13 C20 C24 = CC0301060XX: C/C,10uF,25V,+/-5%,0603; Catalog: 陶瓷电容
C8 C14 C21 C25 = CC0301040XX: C/C,100nF,25V,+/-5%,0603; Remark: NC; Catalog: 陶瓷电容
CON5 = CNDCF0302XX: 小DC电源插座座,DS-002,电源插座3.5-1.3mm，3PIN; Catalog: Connector
CON6 = CNUSM0500XX: Micro USB, B type 5Pin/F SMT; Part Number_AK: CNUSF0900XX; VALUE: MINI_USB_9P; Catalog: Connector
CON7 = CNUSF0502XX: USB-1400-DIP,90 degrees; Catalog: Connector
CON30 = CNHEF0300XX: Header,1X3pin,2.54mm,Female，排母; Catalog: Connector
CON31 = CNHEM0400XX: Header,1X4pin,2.54mm,Male，排针; Remark: NC; Catalog: Connector
D1 = LE03RXX00XX: REDLED,0603; Catalog: 二极管
D2 = DD33ZEN68XX: Zener Diode,UDZS6.8B,6.8V,S0D-323; Catalog: 稳压管
E1-E4 = ED0314000XX: PESD1608H140CR15GPT,0603; ROOM: power; Source_Path: F:\PROJECTFILES\CADENCE\AK9802PLATFORM\AK98XX_MB_V0-0715.DSN; Catalog: ESD Protectors
F1 = SNSMDTS05XX: 保险丝，Littelfuse，0437001.WRA，1A ,1206; Source Path: D:\CADENCE\SPB_16.2\TOOLS\CAPTURE\LIBRARY\DISCRETE.OLB; Catalog: 保险丝
FB1-FB5 = BE0503010XX: BEAD,PZ2012U301-1R5TF,300R,100MHz,0805; Catalog: 贴片磁珠
JP1 JP2 JP5 = CNHEM0300XX: Header,1X3pin,2.54mm,Male，排针; Catalog: Connector
L1-L3 = WL1C04R70XX: Part Number_AK: WL1C02R20XX; SOURCE_PATH: E:\工作目录\ORCAD原理图库\ORCAD元件库\磁珠&电感.OLB; Catalog: 贴片电感
Q1 Q2 Q7 Q8 = MS052SW02XX: AO3415-sot23,E-P-CH,GP; PCB DECAL: AO3413_SOT23_GDS_P; Catalog: MOS
R1 R5 R12 = CR0304720XX: Res,4.7K,1/10W,+/-5%,0603; Catalog: 贴片电阻
R2 = CR0350030XX: Res,500K,1/10W,+/-1%,0603
R3 R8 = CR0310030XX: Res,100K,1/10W,+/-1%,0603; Catalog: 贴片电阻
R4 = CR0201020XX: Res,1K,1/16W,+/-5%,0402; Catalog: 贴片电阻
R6 R9 = CR0354930XX: Res,549K,1/10W,+/-1%,0603; Catalog: 贴片电阻
R7 R11 = CR0312030XX: Res,120K,1/10W,+/-1%,0603; Catalog: 贴片电阻
R10 = CR0305110XX: Res,510R,1/10W,+/-5%,0603; Catalog: 贴片电阻
R141 = CR0310020XX: Res,10K,1/10W,+/-1%,0603; Catalog: 贴片电阻
R143 = CR0301020XX: Res,1K,1/10W,+/-5%,0603; Remark: NC; Catalog: 贴片电阻
SW1 = SWPB06000XX: PSB-2201,6pin ,Lockable; Catalog: 开关
U1-U3 = JCSXTPW60XX: PowerIC,PAM,PAM2312AABADJ,SOT23,5pin; Manufacturer #1: XICOR; Sim.Analog.Order: Model$; PCB DECAL: PAM2312_SOT23-5; Catalog: 集成电路
U4 = JCSXTPW61XX: PowerIC,Leadchip,LC1463CB5ATR18 ,SOT23,5pin; PCB_DECAL: XC6228D332VR_SOT23-5; Source_Path: E:\PCB\ANYKA\AK3918E_SC1035\V200\V201\SCH\AK3918E_V201.DSN; PCB DECAL: LC1463CB5ATR15_SOT23-5; Catalog: 集成电路

## Sheet TF_PA_UART.SchDoc: EVB_MBD_AK376xE_V1.0.1
size A3; Revision: V1.0.1; SheetNumber: 5; SheetTotal: 8
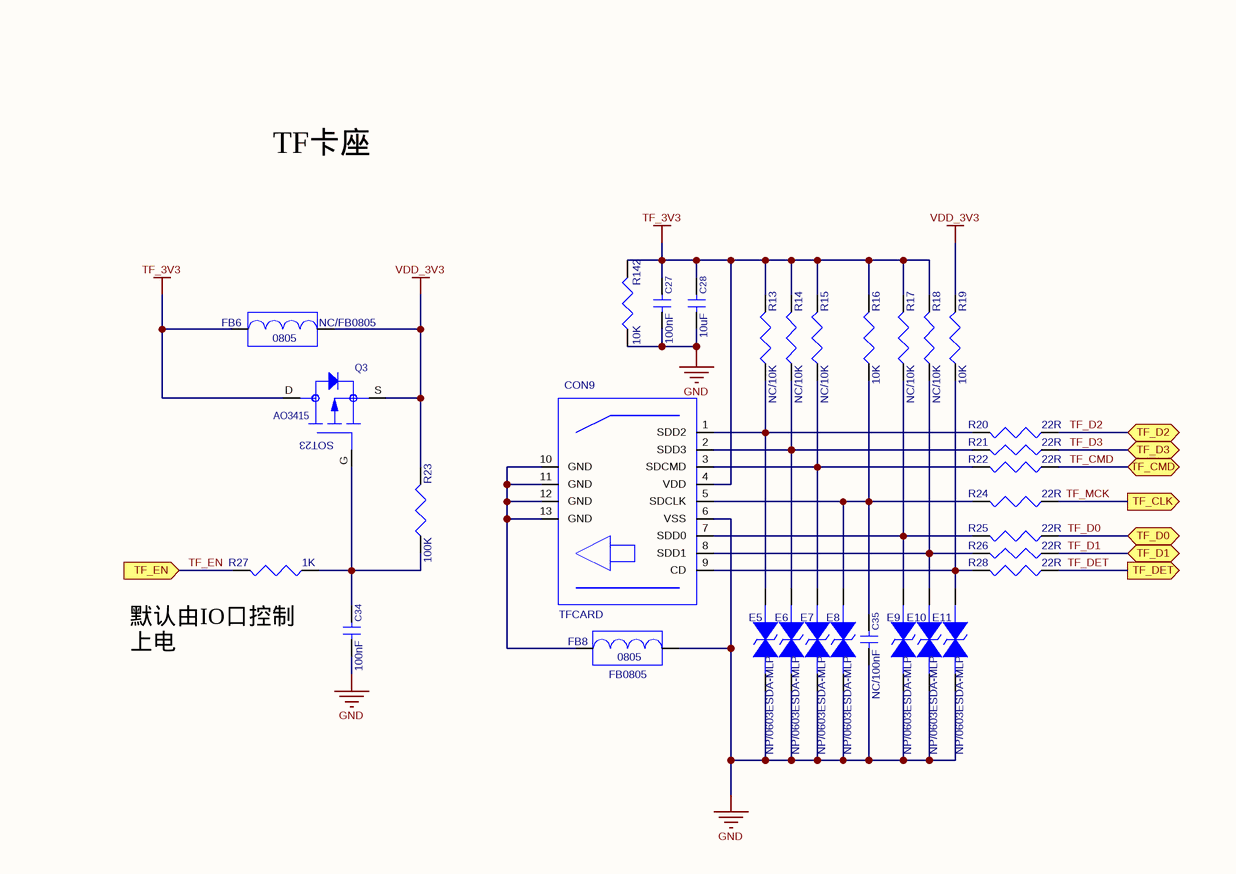
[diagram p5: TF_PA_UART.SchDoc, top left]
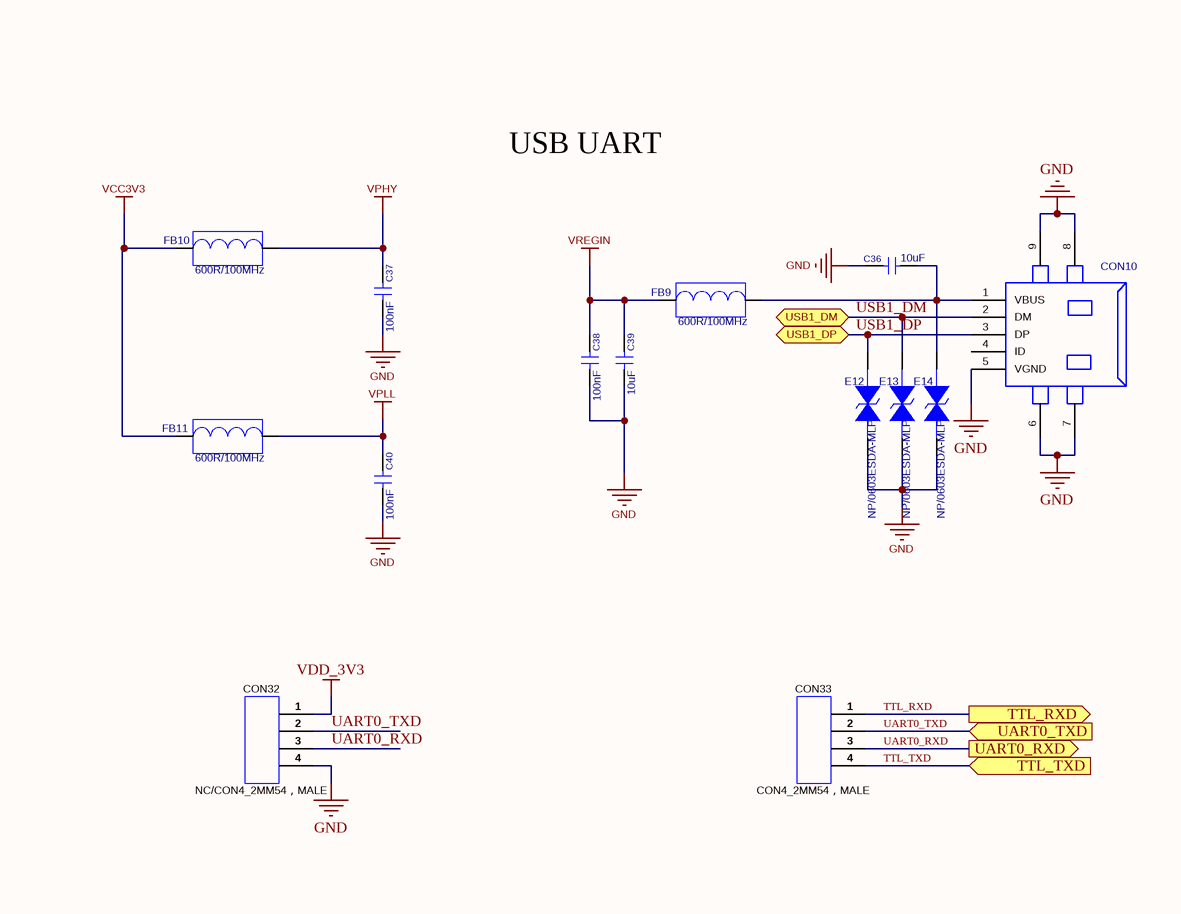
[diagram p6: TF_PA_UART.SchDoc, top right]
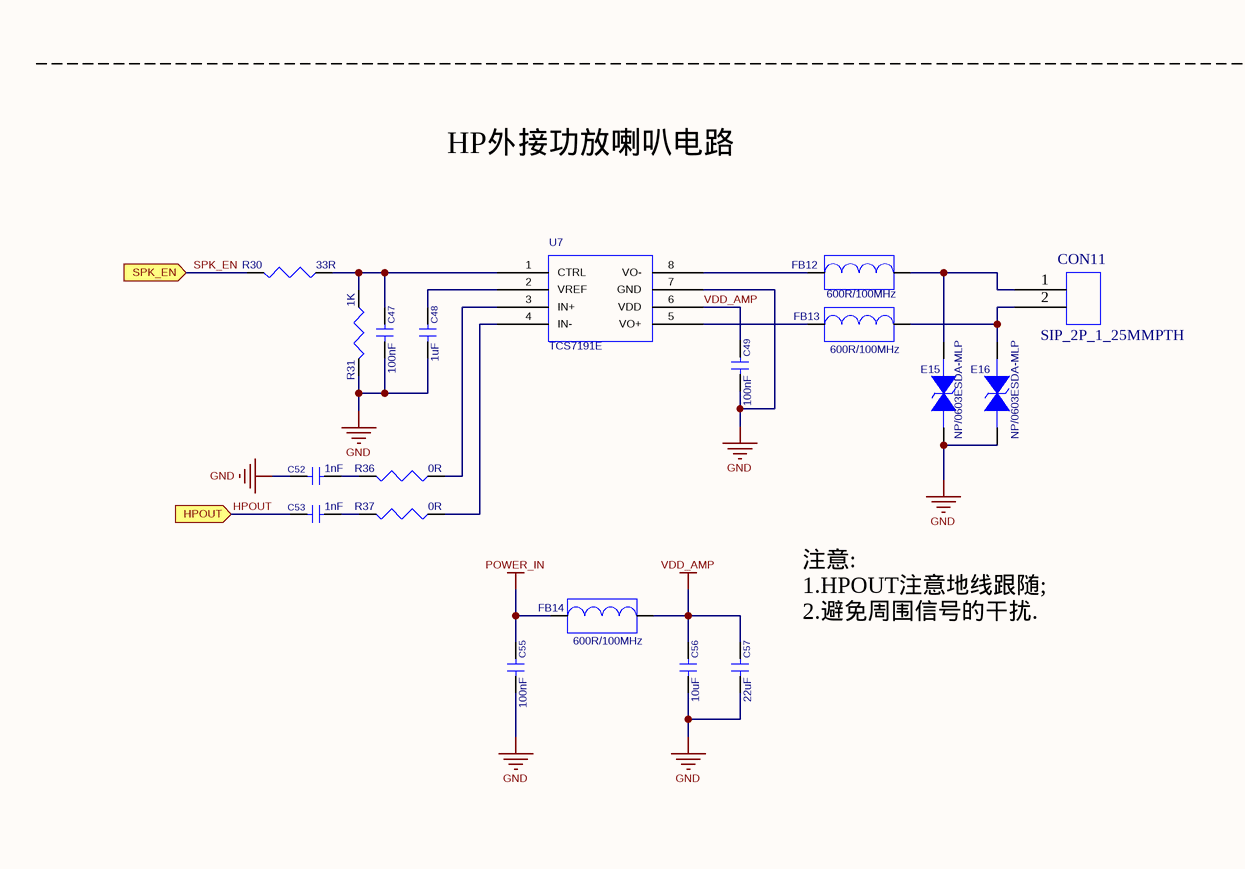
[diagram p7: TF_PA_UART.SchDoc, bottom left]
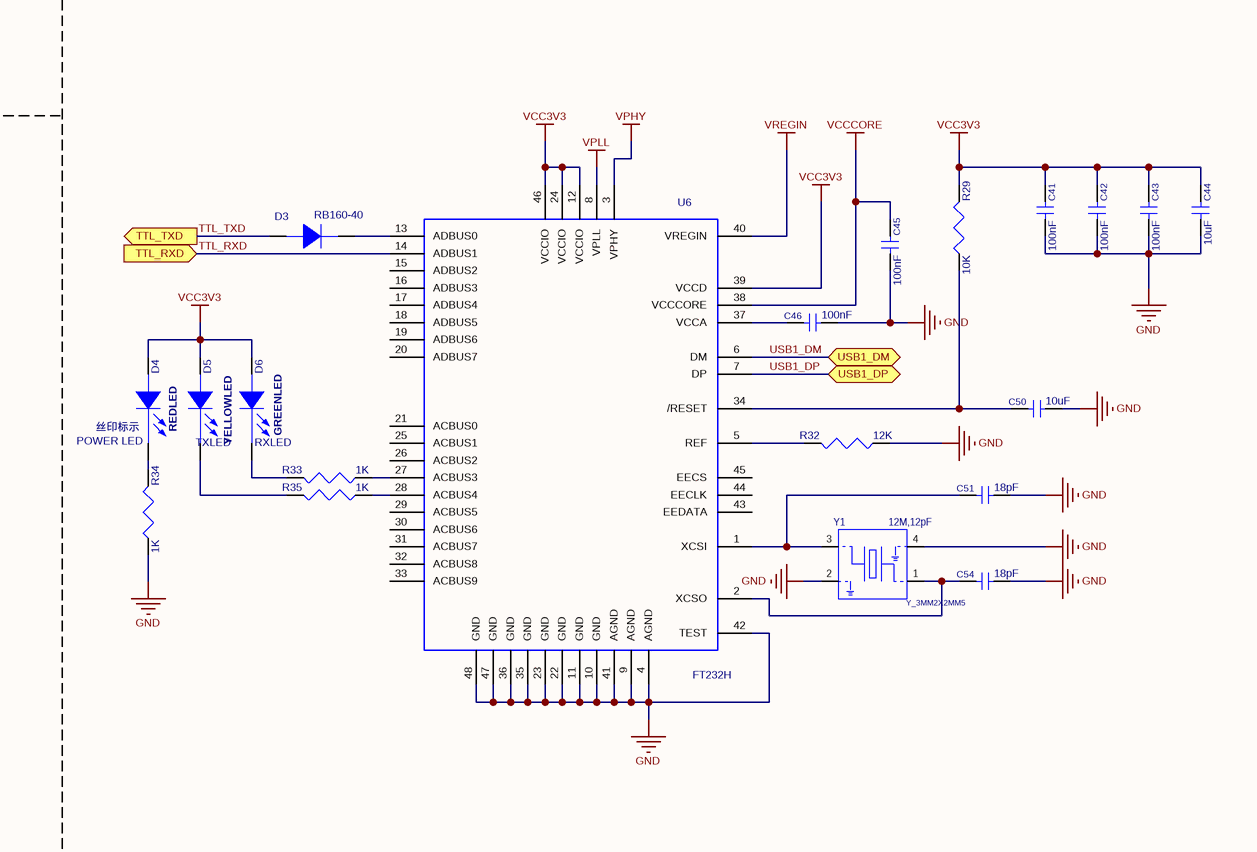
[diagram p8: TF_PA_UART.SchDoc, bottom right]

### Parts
C27  100nF  [C0603]
C28  10uF  [C0603]
C34  100nF  [C0603]
C35  NC/100nF  [C0603]
C36  10uF  [C0603]
C37  100nF  [C0603]
C38  100nF  [C0603]
C39  10uF  [C0603]
C40  100nF  [C0603]
C41  100nF  [C0603]
C42  100nF  [C0603]
C43  100nF  [C0603]
C44  10uF  [C0603]
C45  100nF  [C0603]
C46  100nF  [C0603]
C47  100nF  [C0603]
C48  1uF  [C0603]
C49  100nF  [C0603]
C50  10uF  [C0603]
C51  18pF  [C0603]
C52  1nF  [C0603]
C53  1nF  [C0603]
C54  18pF  [C0603]
C55  100nF  [C0603]
C56  10uF  [C0603]
C57  22uF  [C1206]
CON9  TF_CARD_13P  [TF_CARD_13P]  (value not drawn)
CON10  USB_MICRO-5P/F_SMT  [USB_MICRO_5P/F_SMT]  (value not drawn)
CON11  SIP_2P_1_25MMPTH  [SIP_2P_1_25MMPTH]
CON32  NC/CON4_2MM54，MALE  [CON4_2MM54]
CON33  CON4_2MM54，MALE  [CON4_2MM54]
D3  RB160-40  [RB160-40]
D4  REDLED  [LED0603]
D5  YELLOWLED  [LED0603]
D6  GREENLED  [LED0603]
E5  value NP/0603ESDA-MLP  [ESD0603]  (hidden comment: ESD0603)
E6  value NP/0603ESDA-MLP  [ESD0603]  (hidden comment: ESD0603)
E7  value NP/0603ESDA-MLP  [ESD0603]  (hidden comment: ESD0603)
E8  value NP/0603ESDA-MLP  [ESD0603]  (hidden comment: ESD0603)
E9  value NP/0603ESDA-MLP  [ESD0603]  (hidden comment: ESD0603)
E10  value NP/0603ESDA-MLP  [ESD0603]  (hidden comment: ESD0603)
E11  value NP/0603ESDA-MLP  [ESD0603]  (hidden comment: ESD0603)
E12  value NP/0603ESDA-MLP  [ESD0603]  (hidden comment: ESD0603)
E13  value NP/0603ESDA-MLP  [ESD0603]  (hidden comment: ESD0603)
E14  value NP/0603ESDA-MLP  [ESD0603]  (hidden comment: ESD0603)
E15  value NP/0603ESDA-MLP  [ESD0603]  (hidden comment: ESD0603)
E16  value NP/0603ESDA-MLP  [ESD0603]  (hidden comment: ESD0603)
FB6  value NC/FB0805  [FB0805]  (hidden comment: FB0805)
FB8  FB0805  [FB0805]
FB9  600R/100MHz  [FB0603]
FB10  600R/100MHz  [FB0603]
FB11  600R/100MHz  [FB0603]
FB12  600R/100MHz  [FB0603]
FB13  600R/100MHz  [FB0603]
FB14  600R/100MHz  [FB0603]
Q3  AO3415  [AO3413_SOT23_GDS_P]
R13  NC/10K  [R0603]
R14  NC/10K  [R0603]
R15  NC/10K  [R0603]
R16  10K  [R0603]
R17  NC/10K  [R0603]
R18  NC/10K  [R0603]
R19  10K  [R0603]
R20  22R  [R0603]
R21  22R  [R0603]
R22  22R  [R0603]
R23  100K  [R0603]
R24  22R  [R0603]
R25  22R  [R0603]
R26  22R  [R0603]
R27  1K  [R0603]
R28  22R  [R0603]
R29  10K  [R0603]
R30  33R  [R0603]
R31  1K  [R0603]
R32  12K  [R0603]
R33  1K  [R0603]
R34  1K  [R0603]
R35  1K  [R0603]
R36  0R  [R0603]
R37  0R  [R0603]
R142  10K  [R0603]
U6  value FT232H  [FT232HL_QFP48]  (hidden comment: FT232HL_QFP48)
U7  TCS7191E  [TCS7191E]
Y1  value 12M,12pF  [Y_3MM2X2MM5]  (hidden comment: 12MHz,CL=12pF,20ppm,3225)

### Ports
HPOUT (in), SPK_EN (in), TF_CLK (out), TF_CMD (bidir), TF_D0 (bidir), TF_D1 (bidir), TF_D2 (bidir), TF_D3 (bidir), TF_DET (out), TF_EN (in), TTL_RXD (in), TTL_RXD (out), TTL_TXD (in), TTL_TXD (out), UART0_RXD (out), UART0_TXD (in), USB1_DM (bidir), USB1_DP (bidir)

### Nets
GND: C27.2 C28.2 C34.2 C35.2 C36.1 C37.2 C38.2 C39.2 C40.2 C41.2 C42.2 C43.2 C44.2 C45.2 C46.2 C47.2 C48.2 C49.2 C50.2 C51.2 C52.1 C54.2 C55.2 C56.2 C57.2 CON9.6(VSS) CON10.5(VGND) CON10.6 CON10.7 CON10.8 CON10.9 CON32.4 E5.2 E6.2 E7.2 E8.2 E9.2 E10.2 E11.2 E12.2 E13.2 E14.2 E15.2 E16.2 FB8.2 R31.2 R32.1 R34.1 R142.1 U6.4(AGND) U6.9(AGND) U6.10(GND) U6.11(GND) U6.22(GND) U6.23(GND) U6.35(GND) U6.36(GND) U6.41(AGND) U6.42(TEST) U6.47(GND) U6.48(GND) U7.7(GND) Y1.2 Y1.4
POWER_IN: C55.1 FB14.1
TF_3V3: C27.1 C28.1 CON9.4(VDD) FB6.1 Q3.D R13.2 R14.2 R15.2 R16.2 R17.2 R18.2 R142.2
VCC3V3: C41.1 C42.1 C43.1 C44.1 D4.A D5.A D6.A FB10.1 FB11.1 R29.2 U6.12(VCCIO) U6.24(VCCIO) U6.39(VCCD) U6.46(VCCIO)
VCCCORE: C45.1 U6.38(VCCCORE)
VDD_3V3: CON32.1 FB6.2 Q3.S R19.2 R23.2
VDD_AMP: C49.1 C56.1 C57.1 FB14.2 U7.6(VDD)
VPHY: C37.1 FB10.2 U6.3(VPHY)
VPLL: C40.1 FB11.2 U6.8(VPLL)
VREGIN: C38.1 C39.1 FB9.1 U6.40(VREGIN)
HPOUT: C53.1 ; port HPOUT
SPK_EN: R30.2 ; port SPK_EN
TF_CMD: R22.1 ; port TF_CMD
TF_D0: R25.1 ; port TF_D0
TF_D1: R26.1 ; port TF_D1
TF_D2: R20.1 ; port TF_D2
TF_D3: R21.1 ; port TF_D3
TF_DET: R28.1 ; port TF_DET
TF_EN: R27.2 ; port TF_EN
TF_MCK: R24.1 ; port TF_CLK
TTL_RXD: CON33.1 U6.14(ADBUS1) ; port TTL_RXD
TTL_TXD: CON33.4 D3.A ; port TTL_TXD
UART0_RXD: CON32.3 CON33.3 ; port UART0_RXD
UART0_TXD: CON32.2 CON33.2 ; port UART0_TXD
USB1_DM: CON10.2(DM) E13.1 U6.6(DM) ; port USB1_DM
USB1_DP: CON10.3(DP) E12.1 U6.7(DP) ; port USB1_DP
NetC34_1: C34.1 Q3.G R23.1 R27.1
NetC35_1: C35.1 CON9.5(SDCLK) E8.1 R16.1 R24.2
NetC36_2: C36.2 CON10.1(VBUS) E14.1 FB9.2
NetC46_1: C46.1 U6.37(VCCA)
NetC47_1: C47.1 R30.1 R31.1 U7.1(CTRL)
NetC48_1: C48.1 U7.2(VREF)
NetC50_1: C50.1 R29.1 U6.34(/RESET)
NetC51_1: C51.1 U6.1(XCSI) Y1.3
NetC52_2: C52.2 R36.2
NetC53_2: C53.2 R37.2
NetC54_1: C54.1 U6.2(XCSO) Y1.1
NetCON9_1: CON9.1(SDD2) E5.1 R13.1 R20.2
NetCON9_2: CON9.2(SDD3) E6.1 R14.1 R21.2
NetCON9_3: CON9.3(SDCMD) E7.1 R15.1 R22.2
NetCON9_7: CON9.7(SDD0) E9.1 R17.1 R25.2
NetCON9_8: CON9.8(SDD1) E10.1 R18.1 R26.2
NetCON9_9: CON9.9(CD) E11.1 R19.1 R28.2
NetCON9_10: CON9.10(GND) CON9.11(GND) CON9.12(GND) CON9.13(GND) FB8.1
NetCON11_1: CON11.1 E15.1 FB12.2
NetCON11_2: CON11.2 E16.1 FB13.2
NetD3_K: D3.K U6.13(ADBUS0)
NetD4_K: D4.K R34.2
NetD5_K: D5.K R35.2
NetD6_K: D6.K R33.2
NetFB12_1: FB12.1 U7.8(VO-)
NetFB13_1: FB13.1 U7.5(VO+)
NetR32_2: R32.2 U6.5(REF)
NetR33_1: R33.1 U6.27(ACBUS3)
NetR35_1: R35.1 U6.28(ACBUS4)
NetR36_1: R36.1 U7.3(IN+)
NetR37_1: R37.1 U7.4(IN-)

Not connected (* = marked no-connect by the designer): CON10 4(ID); U6 15(ADBUS2) 16(ADBUS3) 17(ADBUS4) 18(ADBUS5) 19(ADBUS6) 20(ADBUS7) 21(ACBUS0) 25(ACBUS1) 26(ACBUS2) 29(ACBUS5) 30(ACBUS6) 31(ACBUS7) 32(ACBUS8) 33(ACBUS9) 43(EEDATA) 44(EECLK) 45(EECS)

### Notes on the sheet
- USB UART
- TF卡座
- 默认由IO口控制上电
- HP外接功放喇叭电路
- (near D4) 丝印标示
- (near D4) POWER LED
- (near D5) TXLED
- (near D6) RXLED
- (near C57) 注意:
  1.HPOUT注意地线跟随;
  2.避免周围信号的干扰.

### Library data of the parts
C27 C34 C37 C38 C40-C43 C45-C47 C49 C55 = CC0301040XX: C/C,100nF,25V,+/-5%,0603; Catalog: 陶瓷电容
C28 C36 C39 C44 C50 C56 = CC0301060XX: C/C,10uF,25V,+/-5%,0603; Catalog: 陶瓷电容
C35 = CC0301040XX: as C8 on sheet POWER
C48 = CC0301055XX: C/C,1uF,16V,+/-10%,0603; Catalog: 陶瓷电容
C51 C54 = CC0301800XX: C/C,18pF,25V,+/-5%,0603; Catalog: 陶瓷电容
C52 C53 = CC0301020XX: C/C,1nF,25V,+/-5%,0603; Catalog: 陶瓷电容
C57 = CC0602260XX: C/C,22uF,10V,+/-5%,1206; Catalog: 陶瓷电容
CON9 = CNCJF1300XX: TF CARD Connector,13PADS,外焊型 CKT01-009DM; VALUE: TFCARD_AK98XX_PLATFORM; SOURCE_PATH: E:\工作目录\ORCAD原理图库\ORCAD元件库\SD卡&TF卡&4合1PUSH卡.OLB
CON10 = CNUSM0500XX: as CON6 on sheet POWER
CON11 = CNWAM0202XX: WaferConnector,Male,leyconn,605-0P-S130-02P,1.25mm,2pin
CON32 = CNHEM0400XX: as CON31 on sheet POWER
CON33 = CNHEM0400XX: Header,1X4pin,2.54mm,Male，排针; Catalog: Connector
D3 = DD32SCH00XX: Schottky barrier,RB160M-40,SOD-123; Catalog: 二极管
D4 = LE03RXX00XX: REDLED,0603; Catalog: 二极管
D5 = LE03YXX00XX: YELLOW,LED0603
D6 = LE03GXX00XX: GREENLED,0603; Catalog: 二极管
E5-E14 = ED0314000XX: as E1 on sheet POWER
E15 E16 = ED0314000XX: PESD1608H140CR15GPT,0603; ROOM: power; Source_Path: F:\PROJECTFILES\CADENCE\AK9802PLATFORM\AK98XX_MB_V0-0715.DSN; Remark: NC; Catalog: ESD Protectors
FB6 = BE0503010XX: BEAD,PZ2012U301-1R5TF,300R,100MHz,0805; Remark: NC; Catalog: 贴片磁珠
FB8 = BE0503010XX: as FB1 on sheet POWER
FB9-FB14 = BE0306011XX: BLM18BD601SN1, 600R@100MHz; SOURCE_PATH: D:\PROGRAM FILES\ORCAD\ORCAD_10.5\TOOLS\CAPTURE\LIBRARY\DISCRETE.OLB; Catalog: 贴片磁珠
Q3 = MS052SW02XX: AO3415-sot23,E-P-CH,GP; Catalog: MOS
R13-R15 R17-R19 = CR0310020XX: Res,10K,1/10W,+/-1%,0603; Remark: NC; Catalog: 贴片电阻
R16 R29 R142 = CR0310020XX: Res,10K,1/10W,+/-1%,0603; Catalog: 贴片电阻
R20-R22 R24-R26 R28 = CR0302200XX: Res,22R,1/10W,+/-5%,0603; Catalog: 贴片电阻
R23 = CR0310030XX: Res,100K,1/10W,+/-1%,0603; Catalog: 贴片电阻
R27 R31 R33-R35 = CR0301020XX: Res,1K,1/10W,+/-5%,0603; Catalog: 贴片电阻
R30 = CR0333R00XX: Res,33R,1/10W,+/-1%,0603; Catalog: 贴片电阻
R32 = CR0312020XX: Res,12K,1/10W,+/-1%,0603; Catalog: 贴片电阻
R36 R37 = CR0300000XX: Res,0R,1/10W,+/-5%,0603; Catalog: 贴片电阻
U6 = JCQFPIX00XX: InterfaceIC,FTDI Chip,FT232HL,48pin,LQFP; PCB DECAL: FT232HL_QFP48_0MM5_9X9MM; Catalog: 集成电路
U7 = JCSXPAP01XX: Power Amp,TCS,TCS7191E_SOP8_0MM65_3X5MM; PCB DECAL: PJ145_SOP8_0MM65_3X5MM; Catalog: 集成电路
Y1 = XR0012MS1XX: QR3O12M0000S2012RO,12.000MHz, 12pF,20ppm,3.2mm*2.5mm

## Sheet MAC_EMMC_USBWIFI.SchDoc: EVB_MBD_AK376xE_V1.0.1
size A3; Revision: V1.0.1; SheetNumber: 6; SheetTotal: 8
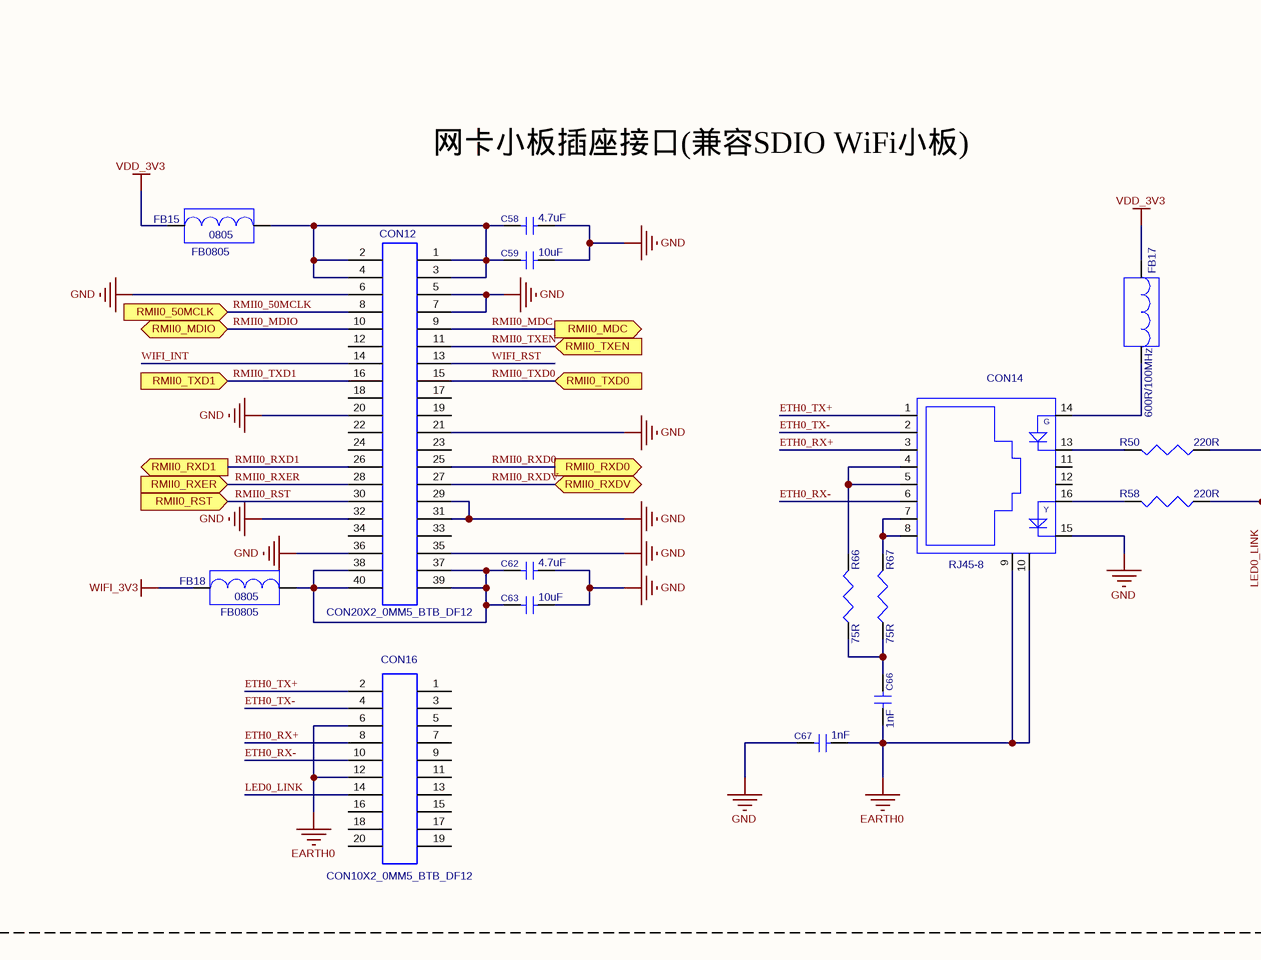
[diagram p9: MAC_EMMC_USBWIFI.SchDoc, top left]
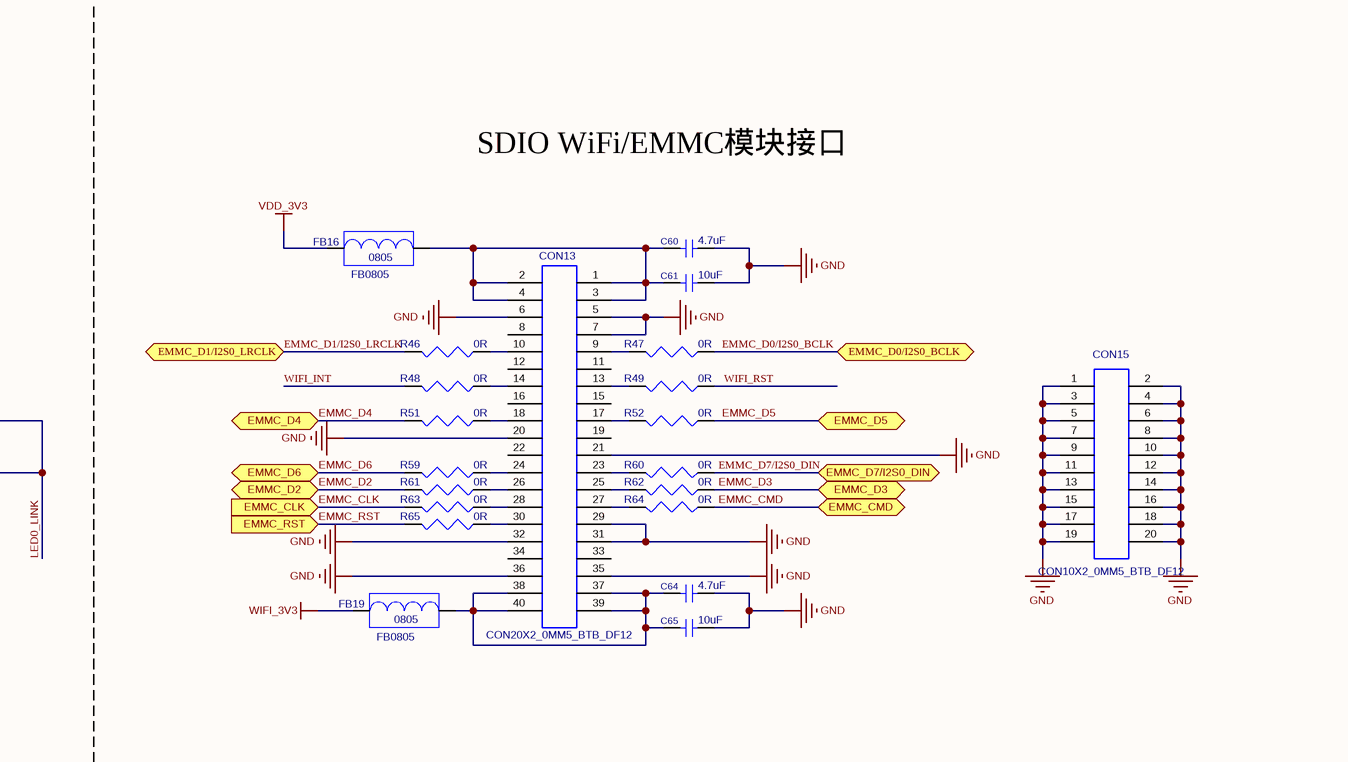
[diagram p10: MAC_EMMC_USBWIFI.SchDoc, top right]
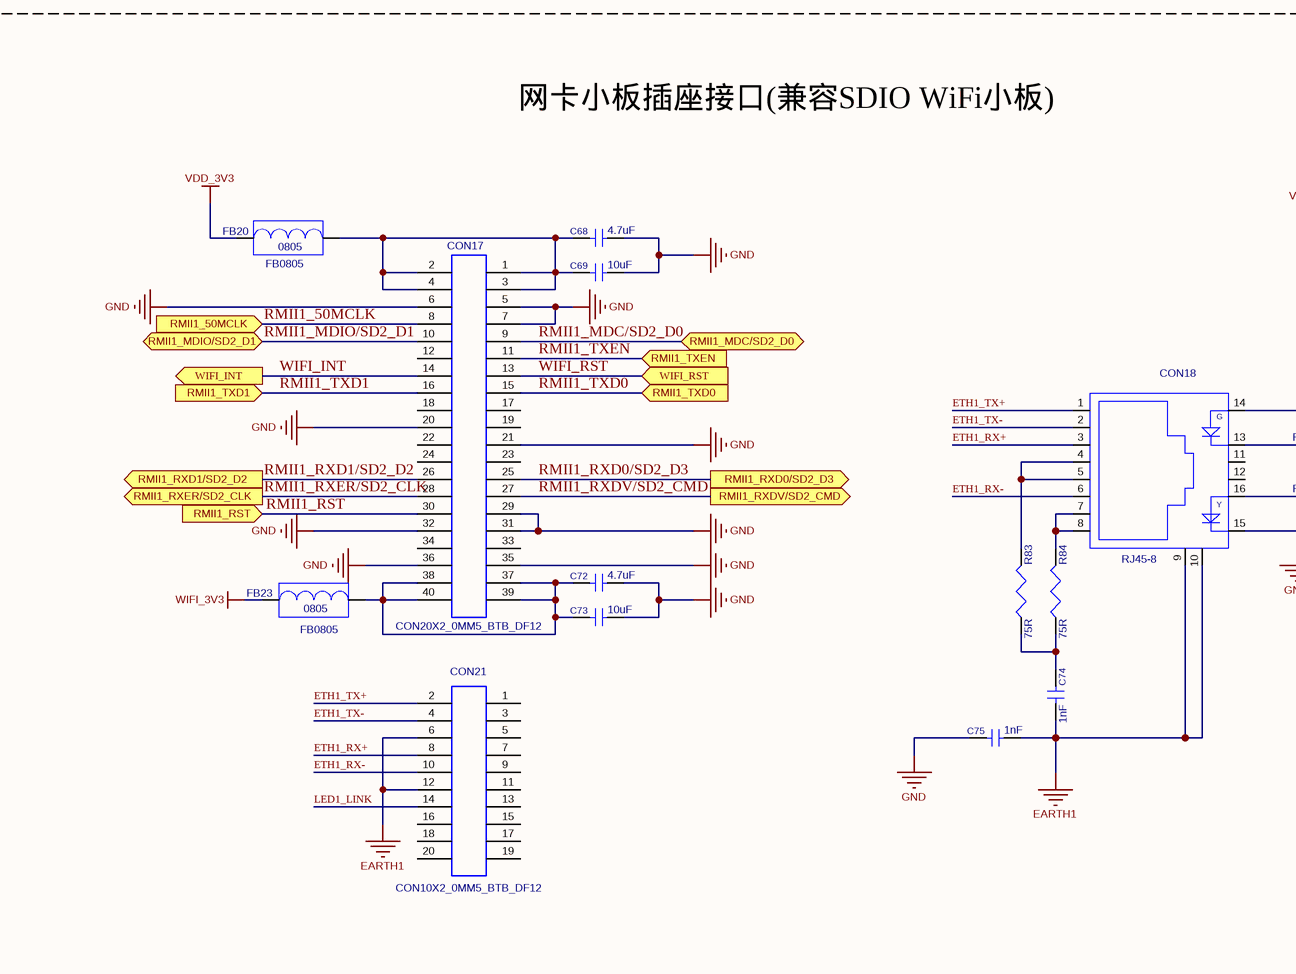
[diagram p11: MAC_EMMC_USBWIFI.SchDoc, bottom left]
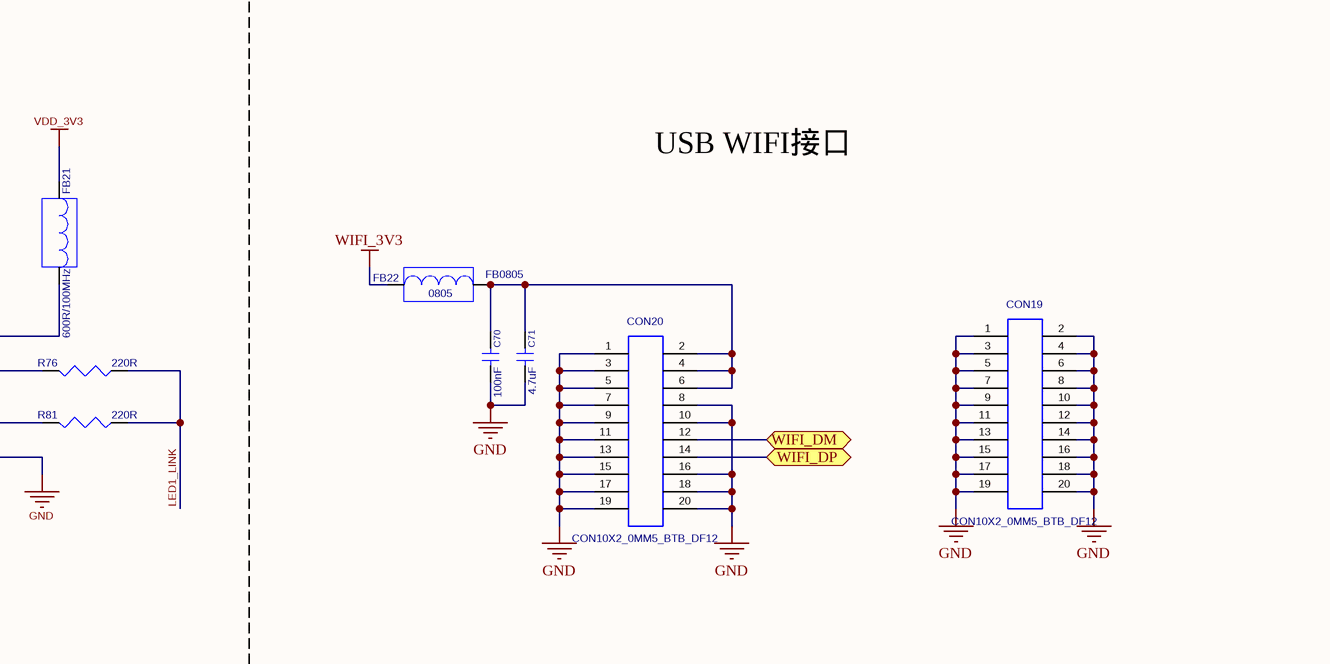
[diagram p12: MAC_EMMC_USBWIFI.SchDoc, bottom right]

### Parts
C58  4.7uF  [C0603]
C59  10uF  [C0603]
C60  4.7uF  [C0603]
C61  10uF  [C0603]
C62  4.7uF  [C0603]
C63  10uF  [C0603]
C64  4.7uF  [C0603]
C65  10uF  [C0603]
C66  1nF  [C1206]
C67  1nF  [C1206]
C68  4.7uF  [C0603]
C69  10uF  [C0603]
C70  100nF  [C0603]
C71  4.7uF  [C0603]
C72  4.7uF  [C0603]
C73  10uF  [C0603]
C74  1nF  [C1206]
C75  1nF  [C1206]
CON12  CON20X2_0MM5_BTB_DF12  [CON20X2_0MM5_BTB_DF12_P]
CON13  CON20X2_0MM5_BTB_DF12  [CON20X2_0MM5_BTB_DF12_P]
CON14  value RJ45-8  [RJ45-8_PTH]  (hidden comment: RJ45-8_PTH)
CON15  CON10X2_0MM5_BTB_DF12  [CON10X2_0MM5_BTB_DF12_P]
CON16  CON10X2_0MM5_BTB_DF12  [CON10X2_0MM5_BTB_DF12_P]
CON17  CON20X2_0MM5_BTB_DF12  [CON20X2_0MM5_BTB_DF12_P]
CON18  value RJ45-8  [RJ45-8_PTH]  (hidden comment: RJ45-8_PTH)
CON19  CON10X2_0MM5_BTB_DF12  [CON10X2_0MM5_BTB_DF12_P]
CON20  CON10X2_0MM5_BTB_DF12  [CON10X2_0MM5_BTB_DF12_P]
CON21  CON10X2_0MM5_BTB_DF12  [CON10X2_0MM5_BTB_DF12_P]
FB15  FB0805  [FB0805]
FB16  FB0805  [FB0805]
FB17  600R/100MHz  [FB0603]
FB18  FB0805  [FB0805]
FB19  FB0805  [FB0805]
FB20  FB0805  [FB0805]
FB21  600R/100MHz  [FB0603]
FB22  FB0805  [FB0805]
FB23  FB0805  [FB0805]
R46  0R  [R0603]
R47  0R  [R0603]
R48  0R  [R0603]
R49  0R  [R0603]
R50  220R  [R0603]
R51  0R  [R0603]
R52  0R  [R0603]
R58  220R  [R0603]
R59  0R  [R0603]
R60  0R  [R0603]
R61  0R  [R0603]
R62  0R  [R0603]
R63  0R  [R0603]
R64  0R  [R0603]
R65  0R  [R0603]
R66  75R  [R0603]
R67  75R  [R0603]
R76  220R  [R0603]
R81  220R  [R0603]
R83  75R  [R0603]
R84  75R  [R0603]

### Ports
EMMC_CLK (in), EMMC_CMD (bidir), EMMC_D0/I2S0_BCLK (bidir), EMMC_D1/I2S0_LRCLK (bidir), EMMC_D2 (bidir), EMMC_D3 (bidir), EMMC_D4 (bidir), EMMC_D5 (bidir), EMMC_D6 (bidir), EMMC_D7/I2S0_DIN (bidir), EMMC_RST (in), RMII0_50MCLK (in), RMII0_MDC (out), RMII0_MDIO (bidir), RMII0_RST (in), RMII0_RXD0 (out), RMII0_RXD1 (out), RMII0_RXDV (bidir), RMII0_RXER (in), RMII0_TXD0 (in), RMII0_TXD1 (in), RMII0_TXEN (in), RMII1_50MCLK (in), RMII1_MDC/SD2_D0 (bidir), RMII1_MDIO/SD2_D1 (bidir), RMII1_RST (in), RMII1_RXD0/SD2_D3 (out), RMII1_RXD1/SD2_D2 (out), RMII1_RXDV/SD2_CMD (out), RMII1_RXER/SD2_CLK (out), RMII1_TXD0 (in), RMII1_TXD1 (in), RMII1_TXEN (in), WIFI_DM (bidir), WIFI_DP (bidir), WIFI_INT (out), WIFI_RST (in)

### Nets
EARTH0: C66.2 C67.2 CON14.9 CON14.10 CON16.6 CON16.12
EARTH1: C74.2 C75.2 CON18.9 CON18.10 CON21.6 CON21.12
GND: C58.2 C59.2 C60.2 C61.2 C62.2 C63.2 C64.2 C65.2 C67.1 C68.2 C69.2 C70.2 C71.2 C72.2 C73.2 C75.1 CON12.5 CON12.6 CON12.7 CON12.20 CON12.21 CON12.29 CON12.31 CON12.32 CON12.35 CON12.36 CON13.5 CON13.6 CON13.7 CON13.20 CON13.21 CON13.29 CON13.31 CON13.32 CON13.35 CON13.36 CON14.15 CON15.1 CON15.2 CON15.3 CON15.4 CON15.5 CON15.6 CON15.7 CON15.8 CON15.9 CON15.10 CON15.11 CON15.12 CON15.13 CON15.14 CON15.15 CON15.16 CON15.17 CON15.18 CON15.19 CON15.20 CON17.5 CON17.6 CON17.7 CON17.20 CON17.21 CON17.29 CON17.31 CON17.32 CON17.35 CON17.36 CON18.15 CON19.1 CON19.2 CON19.3 CON19.4 CON19.5 CON19.6 CON19.7 CON19.8 CON19.9 CON19.10 CON19.11 CON19.12 CON19.13 CON19.14 CON19.15 CON19.16 CON19.17 CON19.18 CON19.19 CON19.20 CON20.1 CON20.3 CON20.5 CON20.7 CON20.8 CON20.9 CON20.10 CON20.11 CON20.13 CON20.15 CON20.16 CON20.17 CON20.18 CON20.19 CON20.20
VDD_3V3: FB15.1 FB16.1 FB17.1 FB20.1 FB21.1
WIFI_3V3: FB18.1 FB19.1 FB22.1 FB23.1
EMMC_CLK: R63.2 ; port EMMC_CLK
EMMC_CMD: R64.1 ; port EMMC_CMD
EMMC_D0/I2S0_BCLK: R47.1 ; port EMMC_D0/I2S0_BCLK
EMMC_D1/I2S0_LRCLK: R46.2 ; port EMMC_D1/I2S0_LRCLK
EMMC_D2: R61.2 ; port EMMC_D2
EMMC_D3: R62.1 ; port EMMC_D3
EMMC_D4: R51.2 ; port EMMC_D4
EMMC_D5: R52.1 ; port EMMC_D5
EMMC_D6: R59.2 ; port EMMC_D6
EMMC_D7/I2S0_DIN: R60.1 ; port EMMC_D7/I2S0_DIN
EMMC_RST: R65.2 ; port EMMC_RST
ETH0_RX+: CON14.3 CON16.8
ETH0_RX-: CON14.6 CON16.10
ETH0_TX+: CON14.1 CON16.2
ETH0_TX-: CON14.2 CON16.4
ETH1_RX+: CON18.3 CON21.8
ETH1_RX-: CON18.6 CON21.10
ETH1_TX+: CON18.1 CON21.2
ETH1_TX-: CON18.2 CON21.4
LED0_LINK: CON16.14 R50.1 R58.1
LED1_LINK: CON21.14 R76.1 R81.1
RMII0_50MCLK: CON12.8 ; port RMII0_50MCLK
RMII0_MDC: CON12.9 ; port RMII0_MDC
RMII0_MDIO: CON12.10 ; port RMII0_MDIO
RMII0_RST: CON12.30 ; port RMII0_RST
RMII0_RXD0: CON12.25 ; port RMII0_RXD0
RMII0_RXD1: CON12.26 ; port RMII0_RXD1
RMII0_RXDV: CON12.27 ; port RMII0_RXDV
RMII0_RXER: CON12.28 ; port RMII0_RXER
RMII0_TXD0: CON12.15 ; port RMII0_TXD0
RMII0_TXD1: CON12.16 ; port RMII0_TXD1
RMII0_TXEN: CON12.11 ; port RMII0_TXEN
RMII1_50MCLK: CON17.8 ; port RMII1_50MCLK
RMII1_MDC/SD2_D0: CON17.9 ; port RMII1_MDC/SD2_D0
RMII1_MDIO/SD2_D1: CON17.10 ; port RMII1_MDIO/SD2_D1
RMII1_RST: CON17.30 ; port RMII1_RST
RMII1_RXD0/SD2_D3: CON17.25 ; port RMII1_RXD0/SD2_D3
RMII1_RXD1/SD2_D2: CON17.26 ; port RMII1_RXD1/SD2_D2
RMII1_RXDV/SD2_CMD: CON17.27 ; port RMII1_RXDV/SD2_CMD
RMII1_RXER/SD2_CLK: CON17.28 ; port RMII1_RXER/SD2_CLK
RMII1_TXD0: CON17.15 ; port RMII1_TXD0
RMII1_TXD1: CON17.16 ; port RMII1_TXD1
RMII1_TXEN: CON17.11 ; port RMII1_TXEN
WIFI_DM: CON20.12 ; port WIFI_DM
WIFI_DP: CON20.14 ; port WIFI_DP
WIFI_INT: CON12.14 CON17.14 R48.2 ; port WIFI_INT
WIFI_RST: CON12.13 CON17.13 R49.1 ; port WIFI_RST
NetC58_1: C58.1 C59.1 CON12.1 CON12.2 CON12.3 CON12.4 FB15.2
NetC60_1: C60.1 C61.1 CON13.1 CON13.2 CON13.3 CON13.4 FB16.2
NetC62_1: C62.1 C63.1 CON12.37 CON12.38 CON12.39 CON12.40 FB18.2
NetC64_1: C64.1 C65.1 CON13.37 CON13.38 CON13.39 CON13.40 FB19.2
NetC66_1: C66.1 R66.1 R67.1
NetC68_1: C68.1 C69.1 CON17.1 CON17.2 CON17.3 CON17.4 FB20.2
NetC70_1: C70.1 C71.1 CON20.2 CON20.4 CON20.6 FB22.2
NetC72_1: C72.1 C73.1 CON17.37 CON17.38 CON17.39 CON17.40 FB23.2
NetC74_1: C74.1 R83.1 R84.1
NetCON13_9: CON13.9 R47.2
NetCON13_10: CON13.10 R46.1
NetCON13_13: CON13.13 R49.2
NetCON13_14: CON13.14 R48.1
NetCON13_17: CON13.17 R52.2
NetCON13_18: CON13.18 R51.1
NetCON13_23: CON13.23 R60.2
NetCON13_24: CON13.24 R59.1
NetCON13_25: CON13.25 R62.2
NetCON13_26: CON13.26 R61.1
NetCON13_27: CON13.27 R64.2
NetCON13_28: CON13.28 R63.1
NetCON13_30: CON13.30 R65.1
NetCON14_4: CON14.4 CON14.5 R66.2
NetCON14_7: CON14.7 CON14.8 R67.2
NetCON14_13: CON14.13 R50.2
NetCON14_14: CON14.14 FB17.2
NetCON14_16: CON14.16 R58.2
NetCON18_4: CON18.4 CON18.5 R83.2
NetCON18_7: CON18.7 CON18.8 R84.2
NetCON18_13: CON18.13 R76.2
NetCON18_14: CON18.14 FB21.2
NetCON18_16: CON18.16 R81.2

Not connected (* = marked no-connect by the designer): CON12 12 17 18 19 22 23 24 33 34; CON13 8 11 12 15 16 19 22 33 34; CON14 11(HOLE1) 12(HOLE2); CON16 1 3 5 7 9 11 13 15 16 17 18 19 20; CON17 12 17 18 19 22 23 24 33 34; CON18 11(HOLE1) 12(HOLE2); CON21 1 3 5 7 9 11 13 15 16 17 18 19 20

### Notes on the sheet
- (near C58) 网卡小板插座接口(兼容SDIO WiFi小板)
- SDIO WiFi/EMMC模块接口
- 网卡小板插座接口(兼容SDIO WiFi小板)
- USB WIFI接口

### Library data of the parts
C58 C60 C62 C64 C68 C71 C72 = CC0304750XX: C/C,4.7uF,25V,+/-5%,0603; Catalog: 陶瓷电容
C59 C61 C63 C65 C69 C73 = CC0301060XX: C/C,10uF,25V,+/-5%,0603; Catalog: 陶瓷电容
C66 C67 C74 C75 = CC0601021XX: C/C,1nF,2KV,+/-10%,1206; Catalog: 陶瓷电容
C70 = CC0301040XX: C/C,100nF,25V,+/-5%,0603; Catalog: 陶瓷电容
CON12 CON13 CON17 = CNBBF4000XX: as CON1 on sheet INTERFACE_CORE
CON14 CON18 = CNXXF1200XX: NetConnector,06-05-10-05-02,6.5mmX16.5mm,2-LED,12pin; Part_RNEfNErNEncNE: NJB701; room: ethernet; Source_Path: E:\PROJECTFILES\CADENCE\WINCE\VER1\EPC_AK7801_V1.DSN
CON15 CON16 CON19-CON21 = CNBBF2000XX: Connector 0.5mm ，BTB2*10Pin，SMT，母座，H3.0，DF12#(3.0)-20DP-0.5;; PCB DECAL: CON10X2_0MM5_BTB_DF12_BOTTOM
FB15 FB16 FB18-FB20 FB22 FB23 = BE0503010XX: as FB1 on sheet POWER
FB17 FB21 = BE0306011XX: as FB9 on sheet TF_PA_UART
R46-R49 R51 R52 R59-R65 = CR0300000XX: Res,0R,1/10W,+/-5%,0603; Catalog: 贴片电阻
R50 R58 R76 R81 = CR0302211XX: Res,220R,1/10W,+/-1%,0603; Catalog: 贴片电阻
R66 R67 R83 R84 = CR0307500XX: Res,75R,1/10W,+/-5%,0603; Catalog: 贴片电阻

## Sheet LCD.SchDoc: EVB_MBD_AK376xE_V1.0.1
size A3; Revision: V1.0.1; SheetNumber: 7; SheetTotal: 8
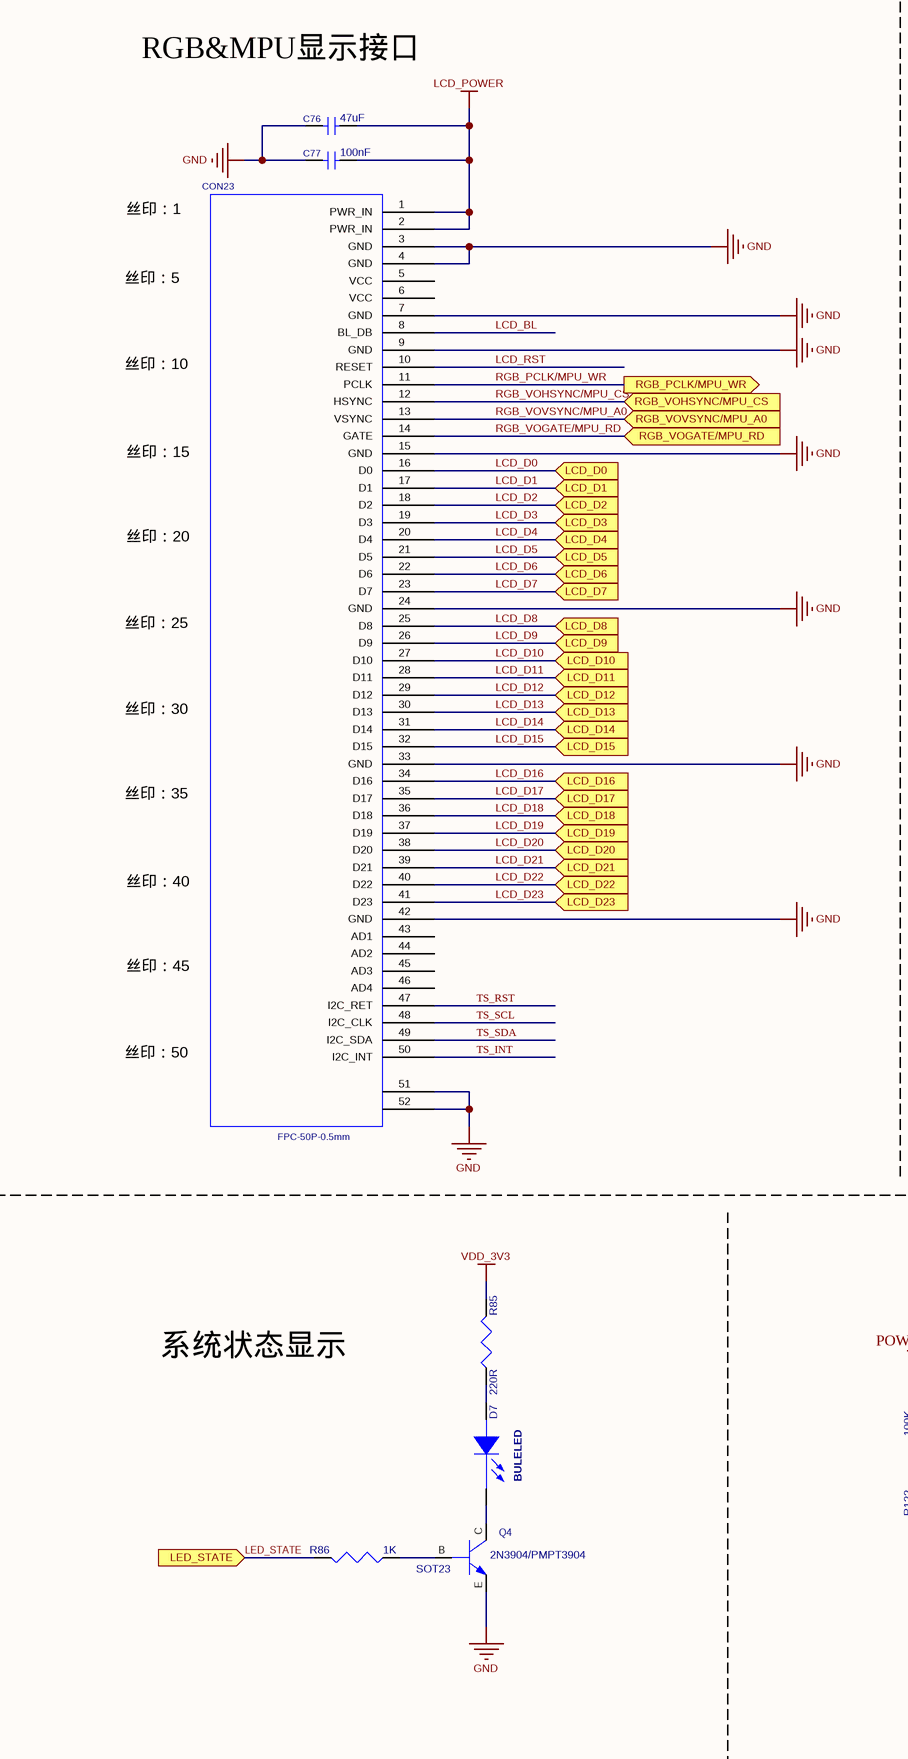
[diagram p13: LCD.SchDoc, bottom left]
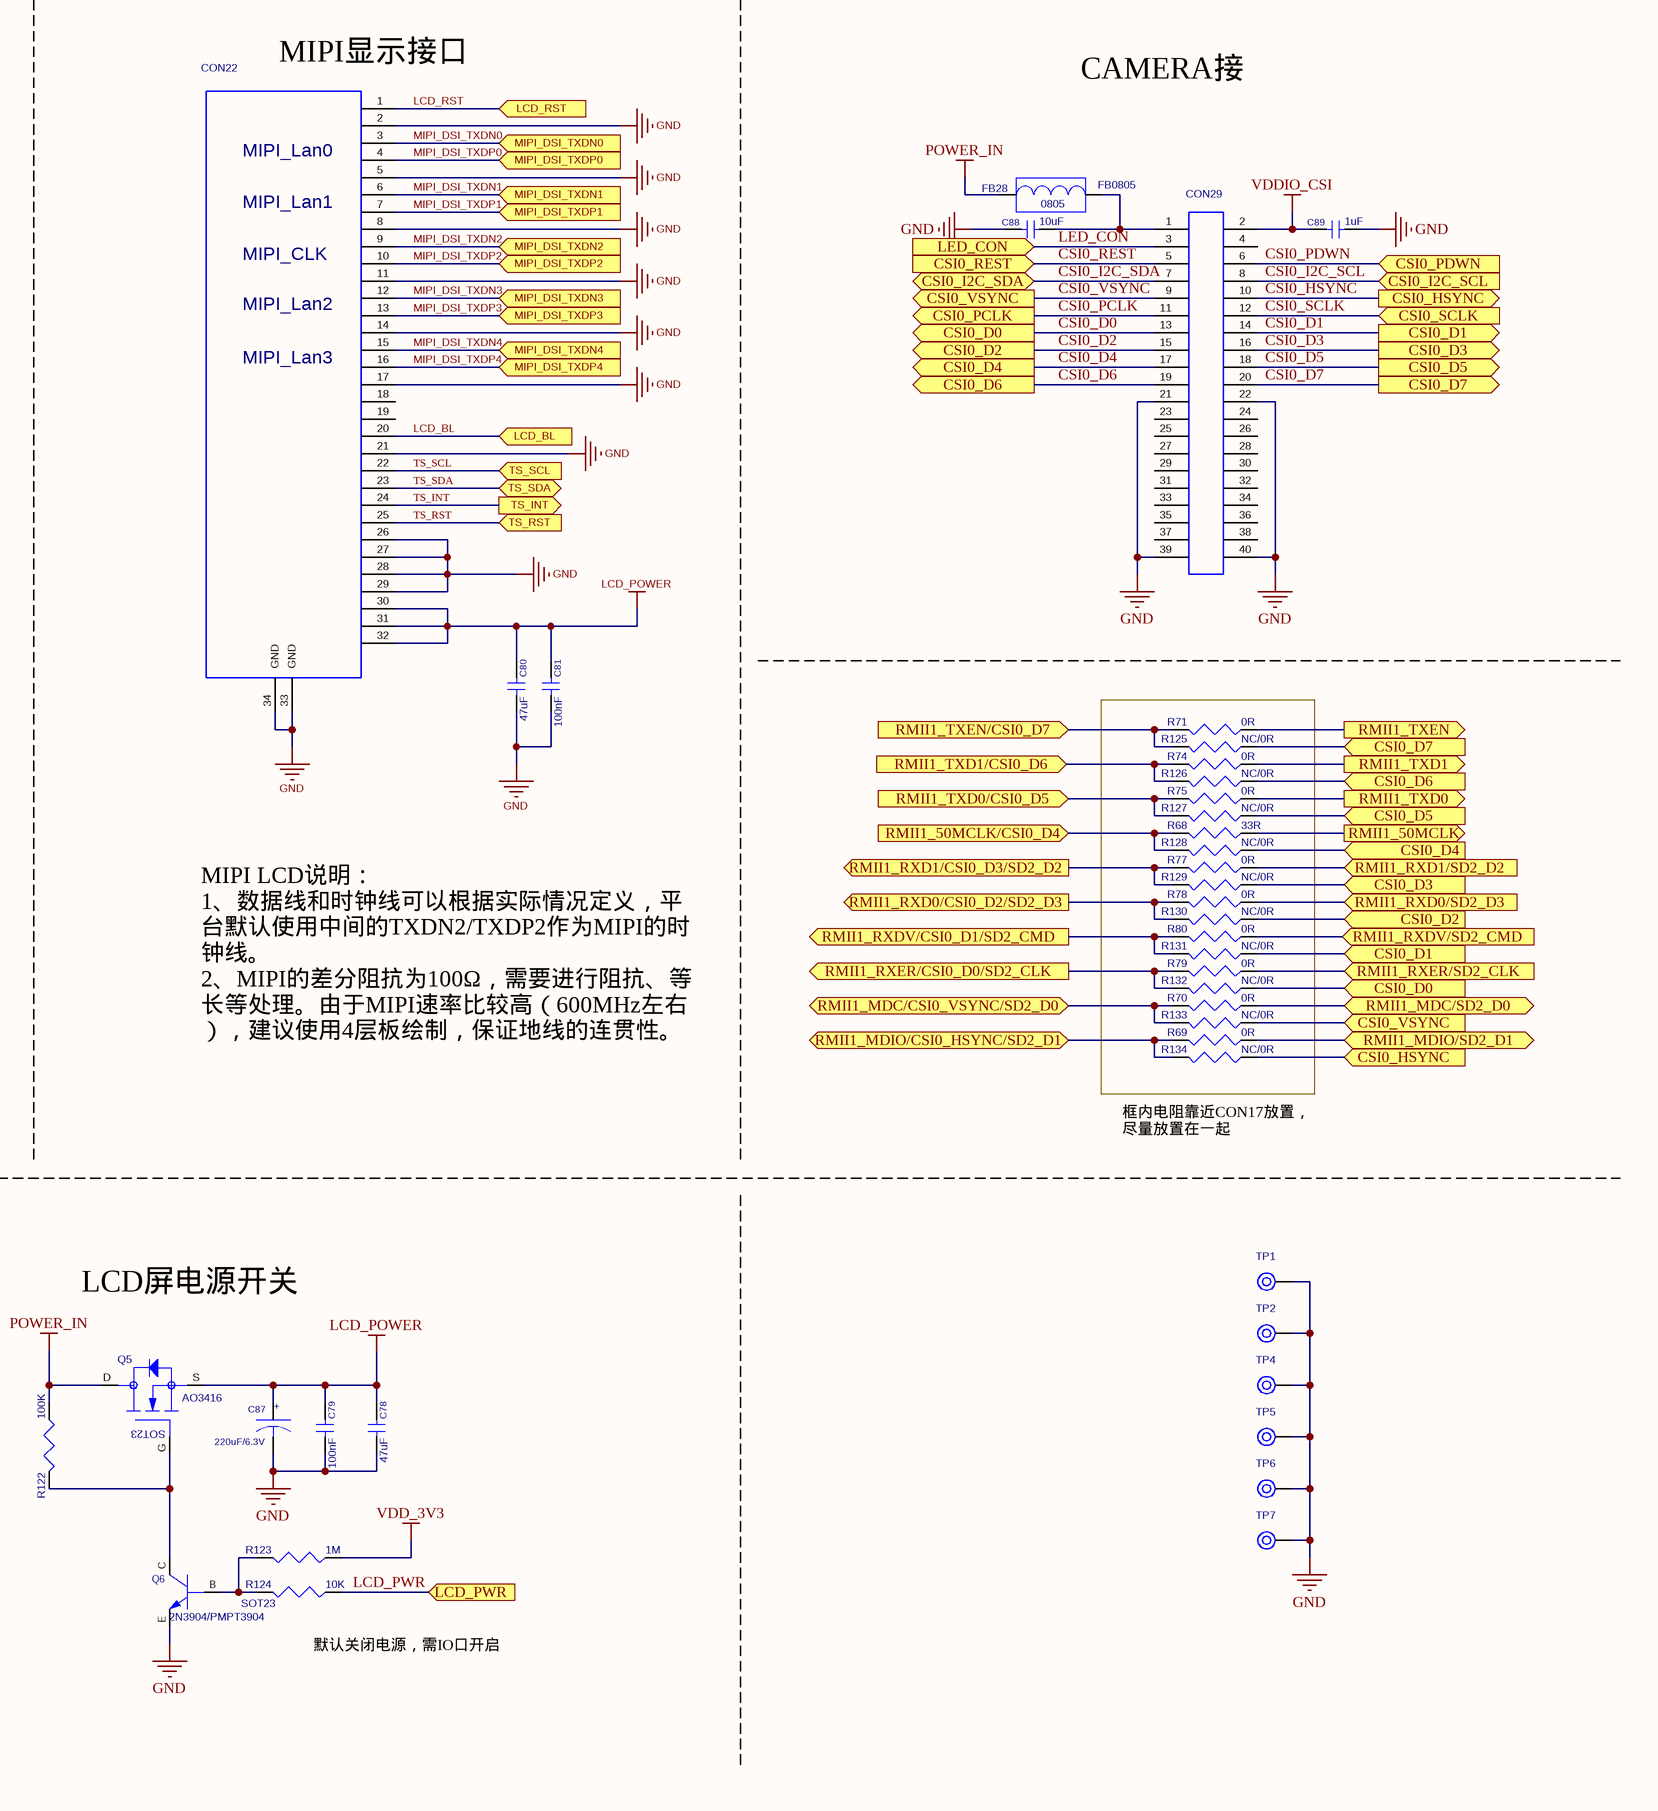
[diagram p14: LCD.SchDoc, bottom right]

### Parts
C76  47uF  [C1210]
C77  100nF  [C0603]
C78  47uF  [C1210]
C79  100nF  [C0603]
C80  47uF  [C1210]
C81  100nF  [C0603]
C87  value 220uF/6.3V  [C3528]  (hidden comment: 220uF)
C88  10uF  [C0603]
C89  1uF  [C0603]
CON22  FPC_32_0MM5  [FPC_32_0MM5]  (value not drawn)
CON23  FPC-50P-0.5MM  [FPC-50P-0.5MM]
CON29  CON20X2_2MM54  [CON20X2_2MM54]  (value not drawn)
D7  BULELED  [LED0603]
FB28  FB0805  [FB0805]
Q4  value 2N3904/PMPT3904  [2N3904/PMBT3904]  (hidden comment: 2N3904/PMBT3904)
Q5  AO3416  [SOT23_GDS]
Q6  value 2N3904/PMPT3904  [2N3904/PMBT3904]  (hidden comment: 2N3904/PMBT3904)
R68  33R  [R0603]
R69  0R  [R0603]
R70  0R  [R0603]
R71  0R  [R0603]
R74  0R  [R0603]
R75  0R  [R0603]
R77  0R  [R0603]
R78  0R  [R0603]
R79  0R  [R0603]
R80  0R  [R0603]
R85  220R  [R0603]
R86  1K  [R0603]
R122  100K  [R0603]
R123  1M  [R0603]
R124  10K  [R0603]
R125  NC/0R  [R0603]
R126  NC/0R  [R0603]
R127  NC/0R  [R0603]
R128  NC/0R  [R0603]
R129  NC/0R  [R0603]
R130  NC/0R  [R0603]
R131  NC/0R  [R0603]
R132  NC/0R  [R0603]
R133  NC/0R  [R0603]
R134  NC/0R  [R0603]
TP1  Test Point  [TP48_H32]  (value not drawn)
TP2  Test Point  [TP48_H32]  (value not drawn)
TP4  Test Point  [TP48_H32]  (value not drawn)
TP5  Test Point  [TP48_H32]  (value not drawn)
TP6  Test Point  [TP48_H32]  (value not drawn)
TP7  Test Point  [TP48_H32]  (value not drawn)

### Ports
CSI0_D0 (in), CSI0_D0 (out), CSI0_D1 (in), CSI0_D1 (out), CSI0_D2 (in), CSI0_D2 (out), CSI0_D3 (in), CSI0_D3 (out), CSI0_D4 (in), CSI0_D4 (out), CSI0_D5 (in), CSI0_D5 (out), CSI0_D6 (in), CSI0_D6 (out), CSI0_D7 (in), CSI0_D7 (out), CSI0_HSYNC (in), CSI0_HSYNC (out), CSI0_I2C_SCL (in), CSI0_I2C_SDA (bidir), CSI0_PCLK (out), CSI0_PDWN (in), CSI0_REST (in), CSI0_SCLK (in), CSI0_VSYNC (in), CSI0_VSYNC (out), LCD_BL (in), LCD_D0 (in), LCD_D1 (in), LCD_D2 (in), LCD_D3 (in), LCD_D4 (in), LCD_D5 (in), LCD_D6 (in), LCD_D7 (in), LCD_D8 (in), LCD_D9 (in), LCD_D10 (in), LCD_D11 (in), LCD_D12 (in), LCD_D13 (in), LCD_D14 (in), LCD_D15 (in), LCD_D16 (in), LCD_D17 (in), LCD_D18 (in), LCD_D19 (in), LCD_D20 (in), LCD_D21 (in), LCD_D22 (in), LCD_D23 (in), LCD_PWR (in), LCD_RST (in), LED_CON (in), LED_STATE (in), MIPI_DSI_TXDN0 (in), MIPI_DSI_TXDN1 (in), MIPI_DSI_TXDN2 (in), MIPI_DSI_TXDN3 (in), MIPI_DSI_TXDN4 (in), MIPI_DSI_TXDP0 (in), MIPI_DSI_TXDP1 (in), MIPI_DSI_TXDP2 (in), MIPI_DSI_TXDP3 (in), MIPI_DSI_TXDP4 (in), RGB_PCLK/MPU_WR (out), RGB_VOGATE/MPU_RD (in), RGB_VOHSYNC/MPU_CS (in), RGB_VOVSYNC/MPU_A0 (in), RMII1_50MCLK (out), RMII1_50MCLK/CSI0_D4 (in), RMII1_MDC/CSI0_VSYNC/SD2_D0 (bidir), RMII1_MDC/SD2_D0 (bidir), RMII1_MDIO/CSI0_HSYNC/SD2_D1 (bidir), RMII1_MDIO/SD2_D1 (bidir), RMII1_RXD0/CSI0_D2/SD2_D3 (out), RMII1_RXD0/SD2_D3 (in), RMII1_RXD1/CSI0_D3/SD2_D2 (out), RMII1_RXD1/SD2_D2 (in), RMII1_RXDV/CSI0_D1/SD2_CMD (out), RMII1_RXDV/SD2_CMD (in), RMII1_RXER/CSI0_D0/SD2_CLK (out), RMII1_RXER/SD2_CLK (in), RMII1_TXD0 (out), RMII1_TXD0/CSI0_D5 (in), RMII1_TXD1 (out), RMII1_TXD1/CSI0_D6 (in), RMII1_TXEN (out), RMII1_TXEN/CSI0_D7 (in), TS_INT (out), TS_RST (in), TS_SCL (in), TS_SDA (bidir)

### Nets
GND: C76.1 C77.1 C78.2 C79.2 C80.2 C81.2 C87.2 C88.1 C89.2 CON22.2 CON22.5 CON22.8 CON22.11 CON22.14 CON22.17 CON22.21 CON22.26 CON22.27 CON22.28 CON22.29 CON22.33(GND) CON22.34(GND) CON23.3(GND) CON23.4(GND) CON23.7(GND) CON23.9(GND) CON23.15(GND) CON23.24(GND) CON23.33(GND) CON23.42(GND) CON23.51 CON23.52 CON29.21 CON29.22 CON29.39 CON29.40 Q4.E Q6.E TP1.1 TP2.1 TP4.1 TP5.1 TP6.1 TP7.1
LCD_POWER: C76.2 C77.2 C78.1 C79.1 C80.1 C81.1 C87.1 CON22.30 CON22.31 CON22.32 CON23.1(PWR_IN) CON23.2(PWR_IN) Q5.S
POWER_IN: FB28.1 Q5.D R122.1
VDD_3V3: R85.2 R123.1
VDDIO_CSI: C89.1 CON29.2
CSI0_D0: CON29.13 R132.1 ; port CSI0_D0
CSI0_D1: CON29.14 R131.1 ; port CSI0_D1
CSI0_D2: CON29.15 R130.1 ; port CSI0_D2
CSI0_D3: CON29.16 R129.1 ; port CSI0_D3
CSI0_D4: CON29.17 R128.1 ; port CSI0_D4
CSI0_D5: CON29.18 R127.1 ; port CSI0_D5
CSI0_D6: CON29.19 R126.1 ; port CSI0_D6
CSI0_D7: CON29.20 R125.1 ; port CSI0_D7
CSI0_HSYNC: CON29.10 R134.1 ; port CSI0_HSYNC
CSI0_I2C_SCL: CON29.8 ; port CSI0_I2C_SCL
CSI0_I2C_SDA: CON29.7 ; port CSI0_I2C_SDA
CSI0_PCLK: CON29.11 ; port CSI0_PCLK
CSI0_PDWN: CON29.6 ; port CSI0_PDWN
CSI0_REST: CON29.5 ; port CSI0_REST
CSI0_SCLK: CON29.12 ; port CSI0_SCLK
CSI0_VSYNC: CON29.9 R133.1 ; port CSI0_VSYNC
LCD_BL: CON22.20 CON23.8(BL_DB) ; port LCD_BL
LCD_D0: CON23.16(D0) ; port LCD_D0
LCD_D1: CON23.17(D1) ; port LCD_D1
LCD_D2: CON23.18(D2) ; port LCD_D2
LCD_D3: CON23.19(D3) ; port LCD_D3
LCD_D4: CON23.20(D4) ; port LCD_D4
LCD_D5: CON23.21(D5) ; port LCD_D5
LCD_D6: CON23.22(D6) ; port LCD_D6
LCD_D7: CON23.23(D7) ; port LCD_D7
LCD_D8: CON23.25(D8) ; port LCD_D8
LCD_D9: CON23.26(D9) ; port LCD_D9
LCD_D10: CON23.27(D10) ; port LCD_D10
LCD_D11: CON23.28(D11) ; port LCD_D11
LCD_D12: CON23.29(D12) ; port LCD_D12
LCD_D13: CON23.30(D13) ; port LCD_D13
LCD_D14: CON23.31(D14) ; port LCD_D14
LCD_D15: CON23.32(D15) ; port LCD_D15
LCD_D16: CON23.34(D16) ; port LCD_D16
LCD_D17: CON23.35(D17) ; port LCD_D17
LCD_D18: CON23.36(D18) ; port LCD_D18
LCD_D19: CON23.37(D19) ; port LCD_D19
LCD_D20: CON23.38(D20) ; port LCD_D20
LCD_D21: CON23.39(D21) ; port LCD_D21
LCD_D22: CON23.40(D22) ; port LCD_D22
LCD_D23: CON23.41(D23) ; port LCD_D23
LCD_PWR: R124.1 ; port LCD_PWR
LCD_RST: CON22.1 CON23.10(RESET) ; port LCD_RST
LED_CON: CON29.3 ; port LED_CON
LED_STATE: R86.2 ; port LED_STATE
MIPI_DSI_TXDN0: CON22.3 ; port MIPI_DSI_TXDN0
MIPI_DSI_TXDN1: CON22.6 ; port MIPI_DSI_TXDN1
MIPI_DSI_TXDN2: CON22.9 ; port MIPI_DSI_TXDN2
MIPI_DSI_TXDN3: CON22.12 ; port MIPI_DSI_TXDN3
MIPI_DSI_TXDN4: CON22.15 ; port MIPI_DSI_TXDN4
MIPI_DSI_TXDP0: CON22.4 ; port MIPI_DSI_TXDP0
MIPI_DSI_TXDP1: CON22.7 ; port MIPI_DSI_TXDP1
MIPI_DSI_TXDP2: CON22.10 ; port MIPI_DSI_TXDP2
MIPI_DSI_TXDP3: CON22.13 ; port MIPI_DSI_TXDP3
MIPI_DSI_TXDP4: CON22.16 ; port MIPI_DSI_TXDP4
RGB_PCLK/MPU_WR: CON23.11(PCLK) ; port RGB_PCLK/MPU_WR
RGB_VOGATE/MPU_RD: CON23.14(GATE) ; port RGB_VOGATE/MPU_RD
RGB_VOHSYNC/MPU_CS: CON23.12(HSYNC) ; port RGB_VOHSYNC/MPU_CS
RGB_VOVSYNC/MPU_A0: CON23.13(VSYNC) ; port RGB_VOVSYNC/MPU_A0
RMII1_50MCLK: R68.1 ; port RMII1_50MCLK
RMII1_MDC/SD2_D0: R70.1 ; port RMII1_MDC/SD2_D0
RMII1_MDIO/SD2_D1: R69.1 ; port RMII1_MDIO/SD2_D1
RMII1_RXD0/SD2_D3: R78.1 ; port RMII1_RXD0/SD2_D3
RMII1_RXD1/SD2_D2: R77.1 ; port RMII1_RXD1/SD2_D2
RMII1_RXDV/SD2_CMD: R80.1 ; port RMII1_RXDV/SD2_CMD
RMII1_RXER/SD2_CLK: R79.1 ; port RMII1_RXER/SD2_CLK
RMII1_TXD0: R75.1 ; port RMII1_TXD0
RMII1_TXD1: R74.1 ; port RMII1_TXD1
RMII1_TXEN: R71.1 ; port RMII1_TXEN
TS_INT: CON22.24 CON23.50(I2C_INT) ; port TS_INT
TS_RST: CON22.25 CON23.47(I2C_RET) ; port TS_RST
TS_SCL: CON22.22 CON23.48(I2C_CLK) ; port TS_SCL
TS_SDA: CON22.23 CON23.49(I2C_SDA) ; port TS_SDA
NetC88_2: C88.2 CON29.1 FB28.2
NetCON2_39: R69.2 R134.2 ; port RMII1_MDIO/CSI0_HSYNC/SD2_D1
NetCON2_40: R70.2 R133.2 ; port RMII1_MDC/CSI0_VSYNC/SD2_D0
NetCON2_41: R79.2 R132.2 ; port RMII1_RXER/CSI0_D0/SD2_CLK
NetCON2_43: R80.2 R131.2 ; port RMII1_RXDV/CSI0_D1/SD2_CMD
NetCON2_44: R78.2 R130.2 ; port RMII1_RXD0/CSI0_D2/SD2_D3
NetCON2_46: R77.2 R129.2 ; port RMII1_RXD1/CSI0_D3/SD2_D2
NetCON2_47: R68.2 R128.2 ; port RMII1_50MCLK/CSI0_D4
NetCON2_48: R75.2 R127.2 ; port RMII1_TXD0/CSI0_D5
NetCON2_49: R74.2 R126.2 ; port RMII1_TXD1/CSI0_D6
NetCON2_50: R71.2 R125.2 ; port RMII1_TXEN/CSI0_D7
NetD7_A: D7.A R85.1
NetD7_K: D7.K Q4.C
NetQ4_B: Q4.B R86.1
NetQ5_G: Q5.G Q6.C R122.2
NetQ6_B: Q6.B R123.2 R124.2

Not connected (* = marked no-connect by the designer): CON22 18 19; CON23 5(VCC) 6(VCC) 43(AD1) 44(AD2) 45(AD3) 46(AD4); CON29 4 23 24 25 26 27 28 29 30 31 32 33 34 35 36 37 38

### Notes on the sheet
- (near C76) RGB&MPU显示接口
- (near CON22) MIPI显示接口
- CAMERA接口
- 丝印：1
- (near CON22) MIPI_Lan0
- (near CON22) MIPI_Lan1
- 丝印：5
- (near CON22) MIPI_CLK
- 丝印：10
- (near CON22) MIPI_Lan2
- (near CON22) MIPI_Lan3
- 丝印：15
- 丝印：20
- 丝印：25
- 丝印：30
- 丝印：35
- 丝印：40
- 丝印：45
- 丝印：50
- MIPI LCD说明：
  1、数据线和时钟线可以根据实际情况定义，平台默认使用中间的TXDN2/TXDP2作为MIPI的时钟线。
  2、MIPI的差分阻抗为100Ω，需要进行阻抗、等长等处理。由于MIPI速率比较高（600MHz左右），建议使用4层板绘制，保证地线的连贯性。
- 框内电阻靠近CON17放置，尽量放置在一起
- LCD屏电源开关
- 系统状态显示
- (near R124) 默认关闭电源，需IO口开启

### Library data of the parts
C76 C78 C80 = CC1004760XX: C/C,47uF,10V,+/-10%,1210; Catalog: 陶瓷电容
C77 C79 C81 = CC0301040XX: C/C,100nF,25V,+/-5%,0603; Catalog: 陶瓷电容
C87 = TC2802271XX: T/C,220uF,6.3V,+/-5%,3528; Catalog: 钽电容
C88 = CC0301060XX: C/C,10uF,25V,+/-5%,0603; Catalog: 陶瓷电容
C89 = CC0301055XX: C/C,1uF,16V,+/-10%,0603; Catalog: 陶瓷电容
CON22 = CNFPF3201XX: FPC连接器，32P，0.5mm，翻盖式，下接，H=2mm; PCB DECAL: CON32_0MM5; Catalog: Connector
CON23 = CNFPF5001XX: 连接器 FPC连接器，50P，0.5mm，翻盖式，H=2mm; ROOM: lcd1; Source Path: D:\MAGIC\SCHEMATICS\MAGIC_DAUGHTERBD_EVT_V1.DSN; PCB DECAL: CON50_0MM5; Catalog: Connector
CON29 = CNHEF4601XX: CON2*20&2X1X3,2.54mm,Female，排母; Catalog: Connector
D7 = LE03BXX00XX: BULELED,0603; Catalog: 二极管
FB28 = BE0503010XX: as FB1 on sheet POWER
Q4 Q6 = TR05NGN00XX: 2N3904/PMBT3904,SOT-23,NPN,GP; PCB DECAL: 2N3904/PMBT3904_SOT23_BCE_NPN; Catalog: 三极管
Q5 = JCSXTPW62XX: NMOS,20V,±8V,6.5A,<34mΩ,VGS(th)>1V,SOT-23,AO3416.; PCB DECAL: AO3413_SOT23_GDS_P; Catalog: MOS
R68 = CR0333R00XX: Res,33R,1/10W,+/-1%,0603; Catalog: 贴片电阻
R69-R71 R74 R75 R77-R80 R129 = CR0300000XX: Res,0R,1/10W,+/-5%,0603; Catalog: 贴片电阻
R85 = CR0302211XX: Res,220R,1/10W,+/-1%,0603; Catalog: 贴片电阻
R86 = CR0301020XX: Res,1K,1/10W,+/-5%,0603; Catalog: 贴片电阻
R122 = CR0310030XX: Res,100K,1/10W,+/-1%,0603; Catalog: 贴片电阻
R123 = CR0310040XX: Res,1M,1/10W,+/-1%,0603; Catalog: 贴片电阻
R124 = CR0310020XX: Res,10K,1/10W,+/-1%,0603; Catalog: 贴片电阻
R125-R128 R130-R134 = CR0300000XX: Res,0R,1/10W,+/-5%,0603; Remark: NC; Catalog: 贴片电阻
TP1 TP2 TP4-TP7 = PLDIPTP00XX: 塑料外壳 TestPin,RuiGu,TE-1,hole in PCB:Ф0.9-1.0; Remark: NC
